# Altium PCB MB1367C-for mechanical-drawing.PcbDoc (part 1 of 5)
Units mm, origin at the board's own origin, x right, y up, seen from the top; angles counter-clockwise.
Board outline 70 x 82.5 mm, 4 copper layers (Top Layer, Signal Layer 1, Signal Layer 2, Bottom Layer), stack 1.614 mm thick; 191 components, 143 nets, 808 pads, 920 vias.
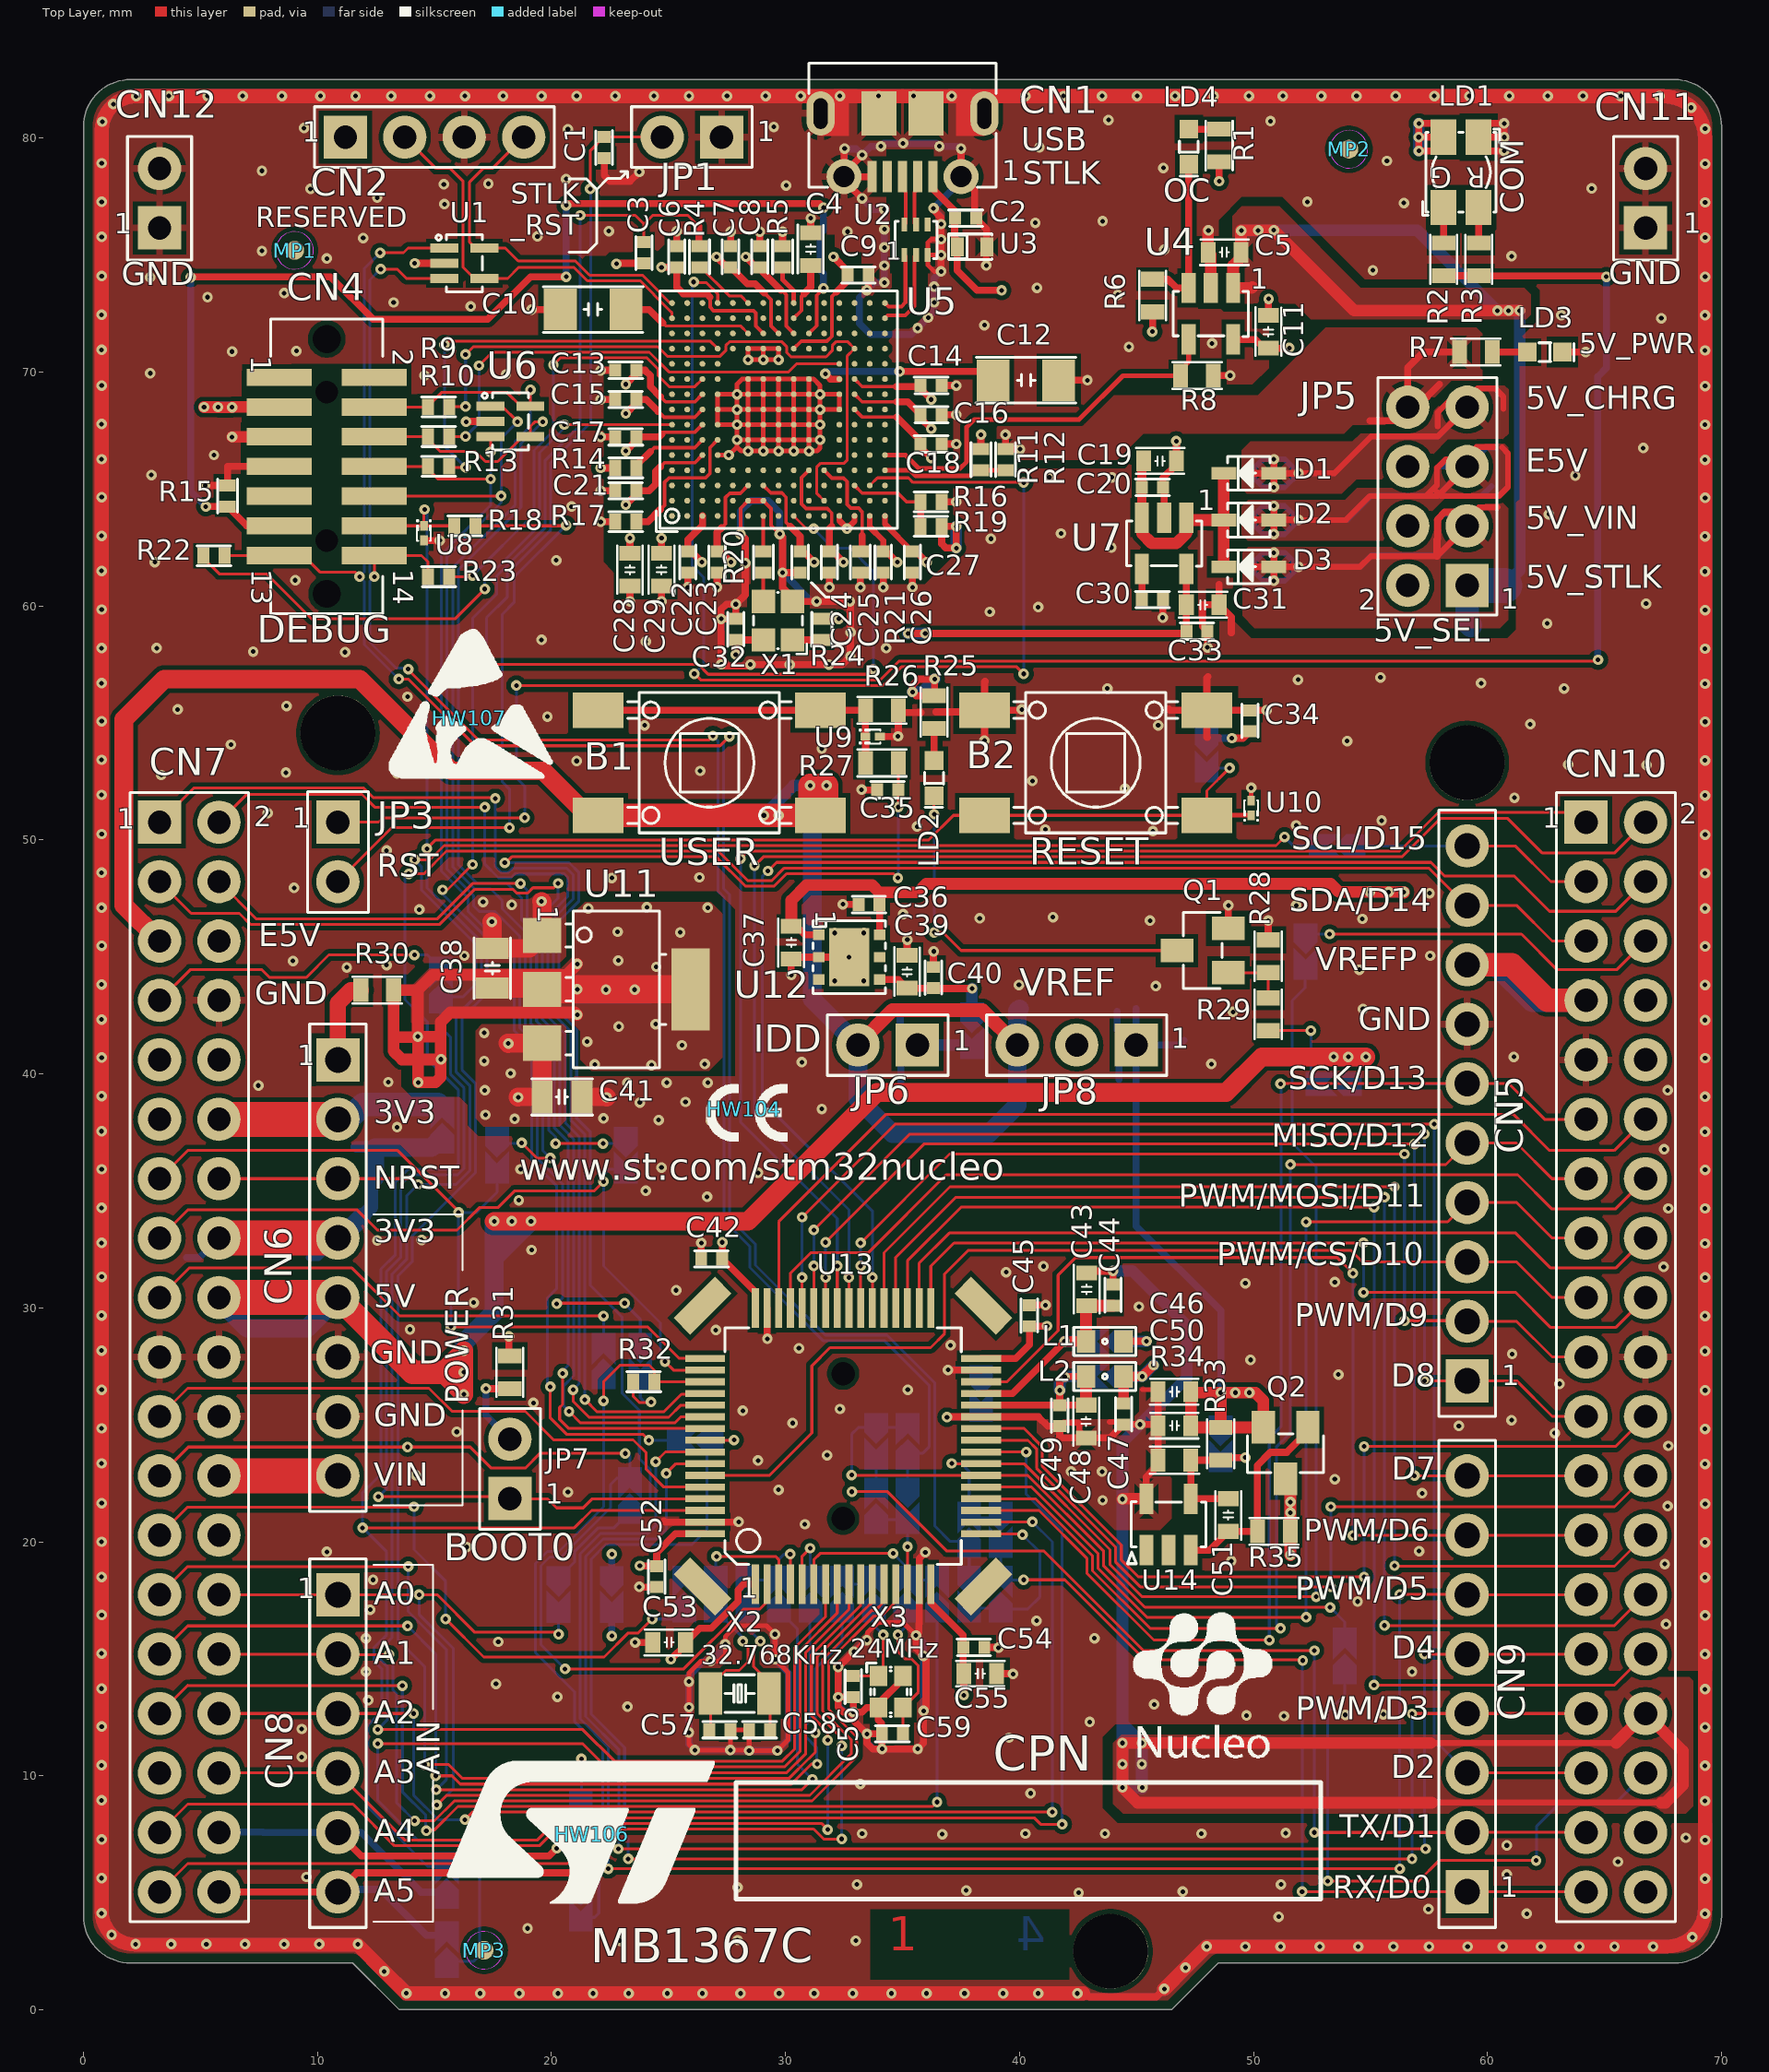
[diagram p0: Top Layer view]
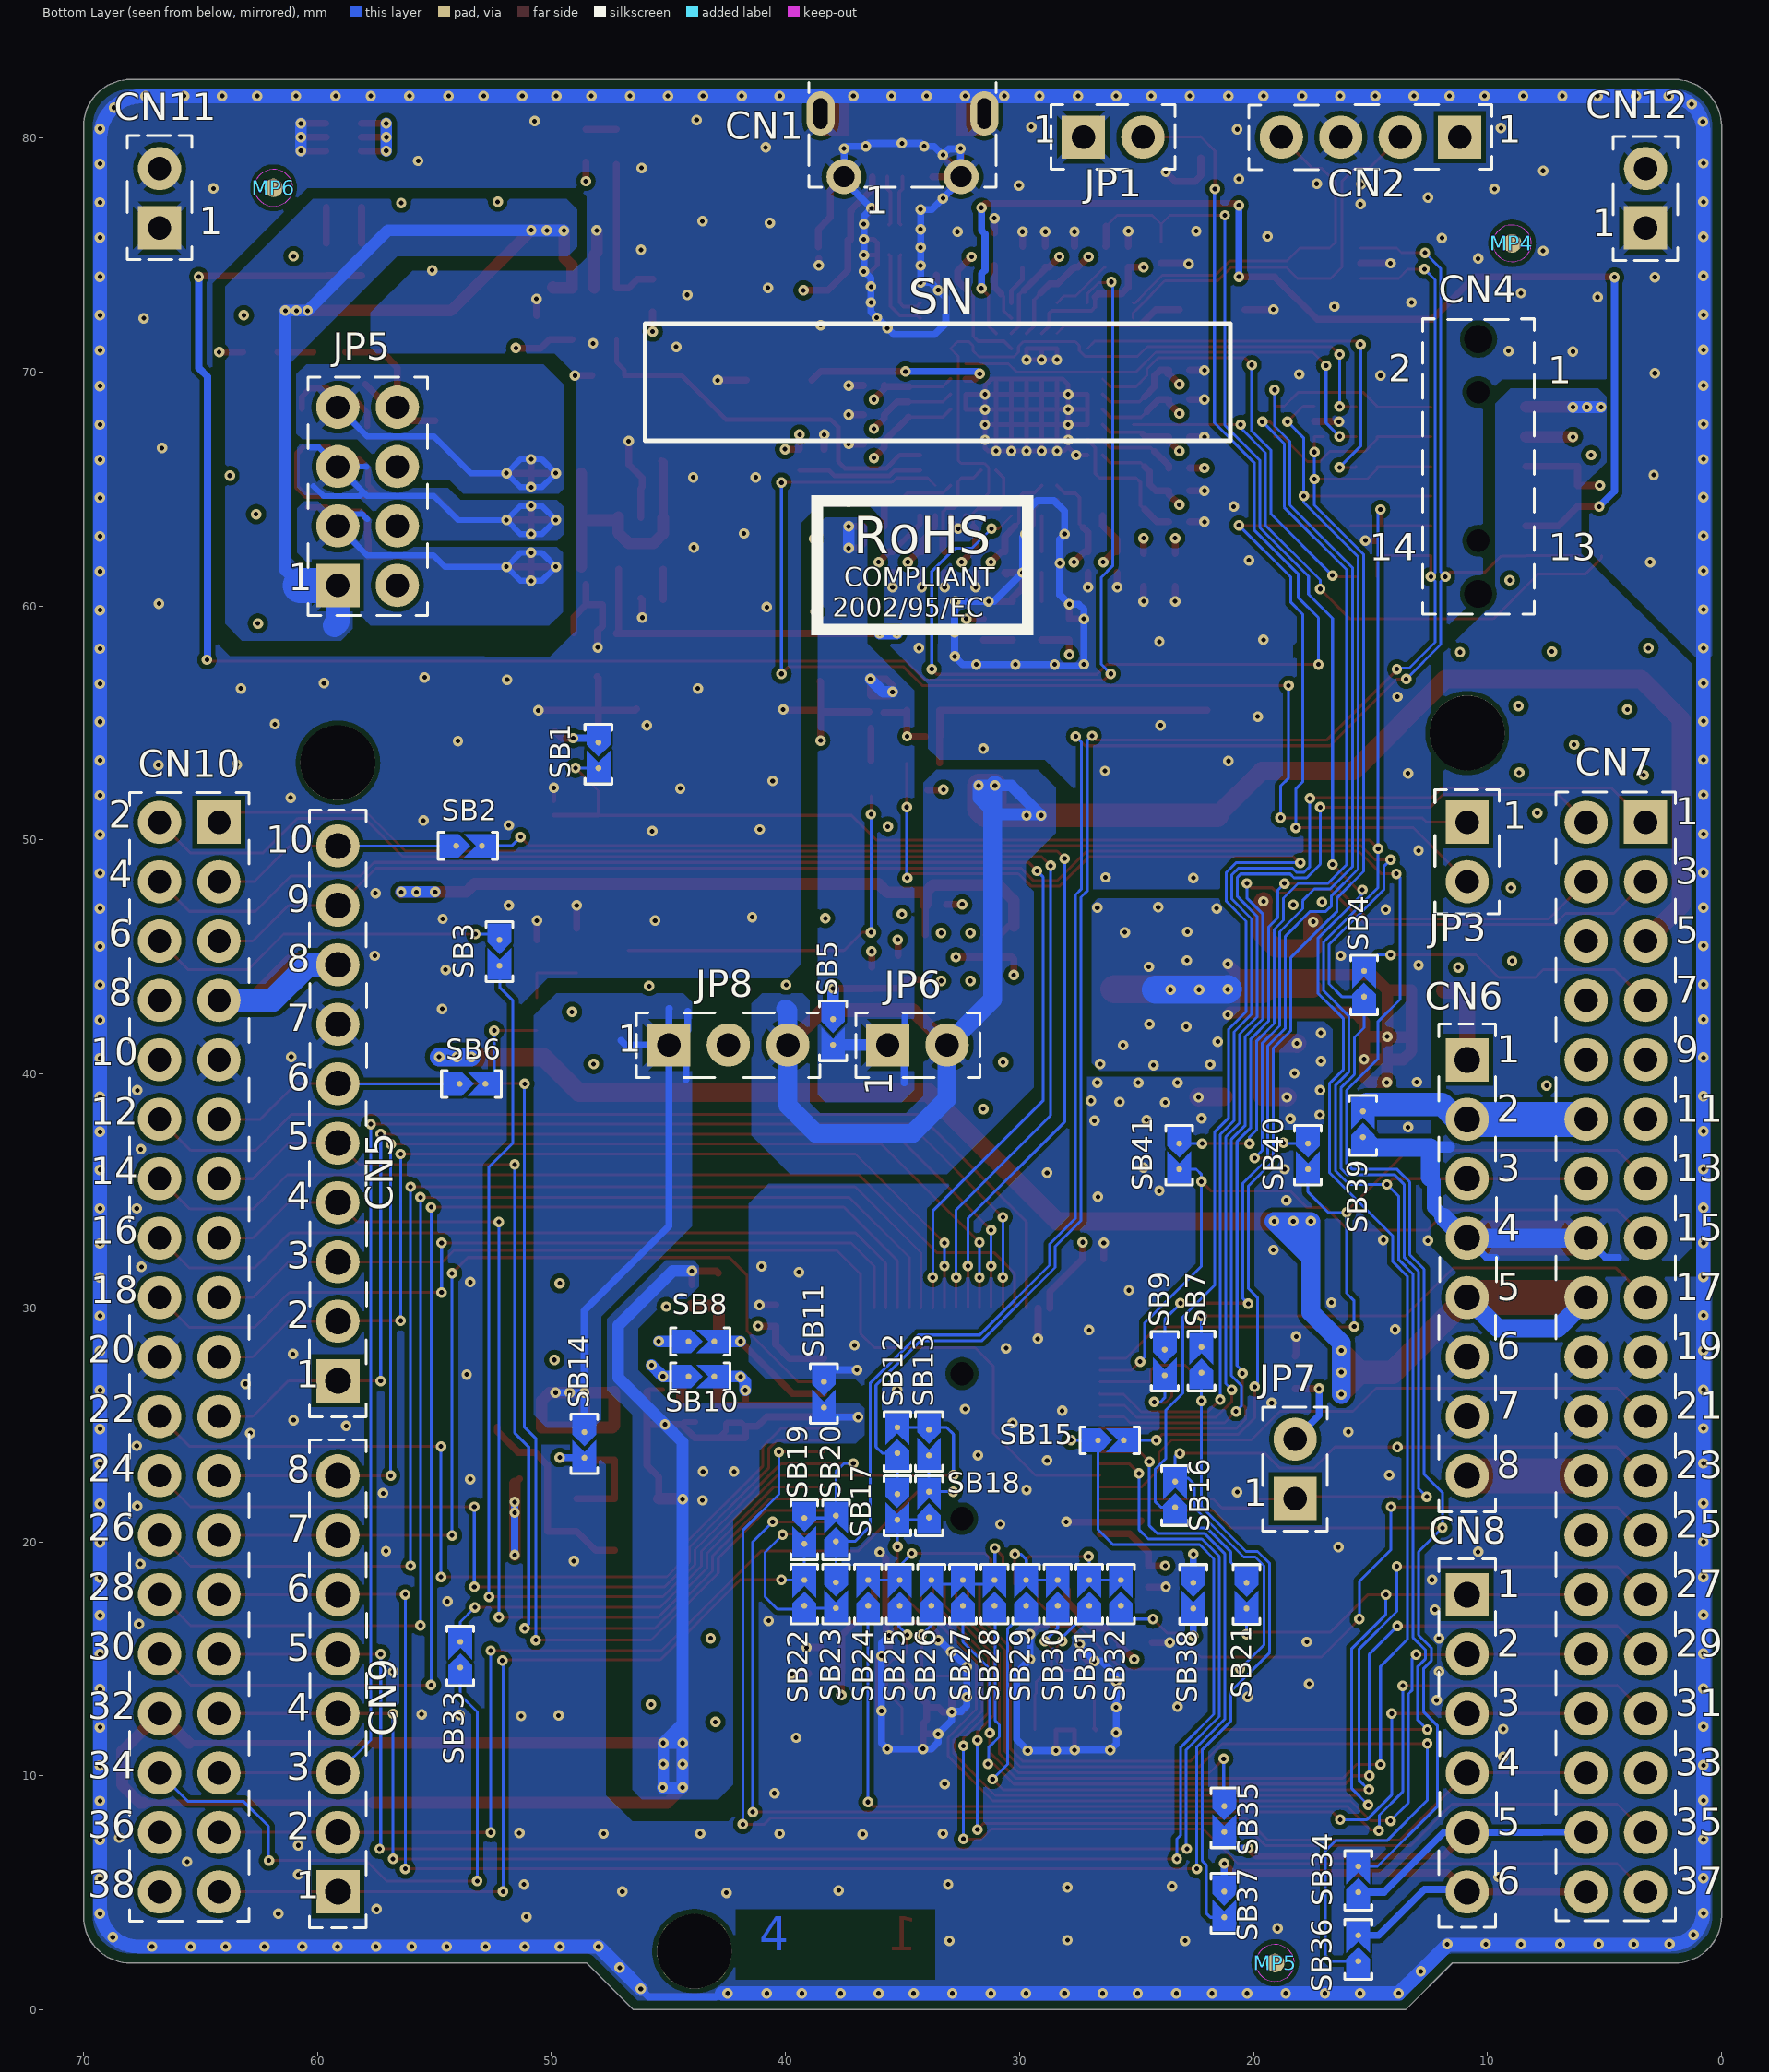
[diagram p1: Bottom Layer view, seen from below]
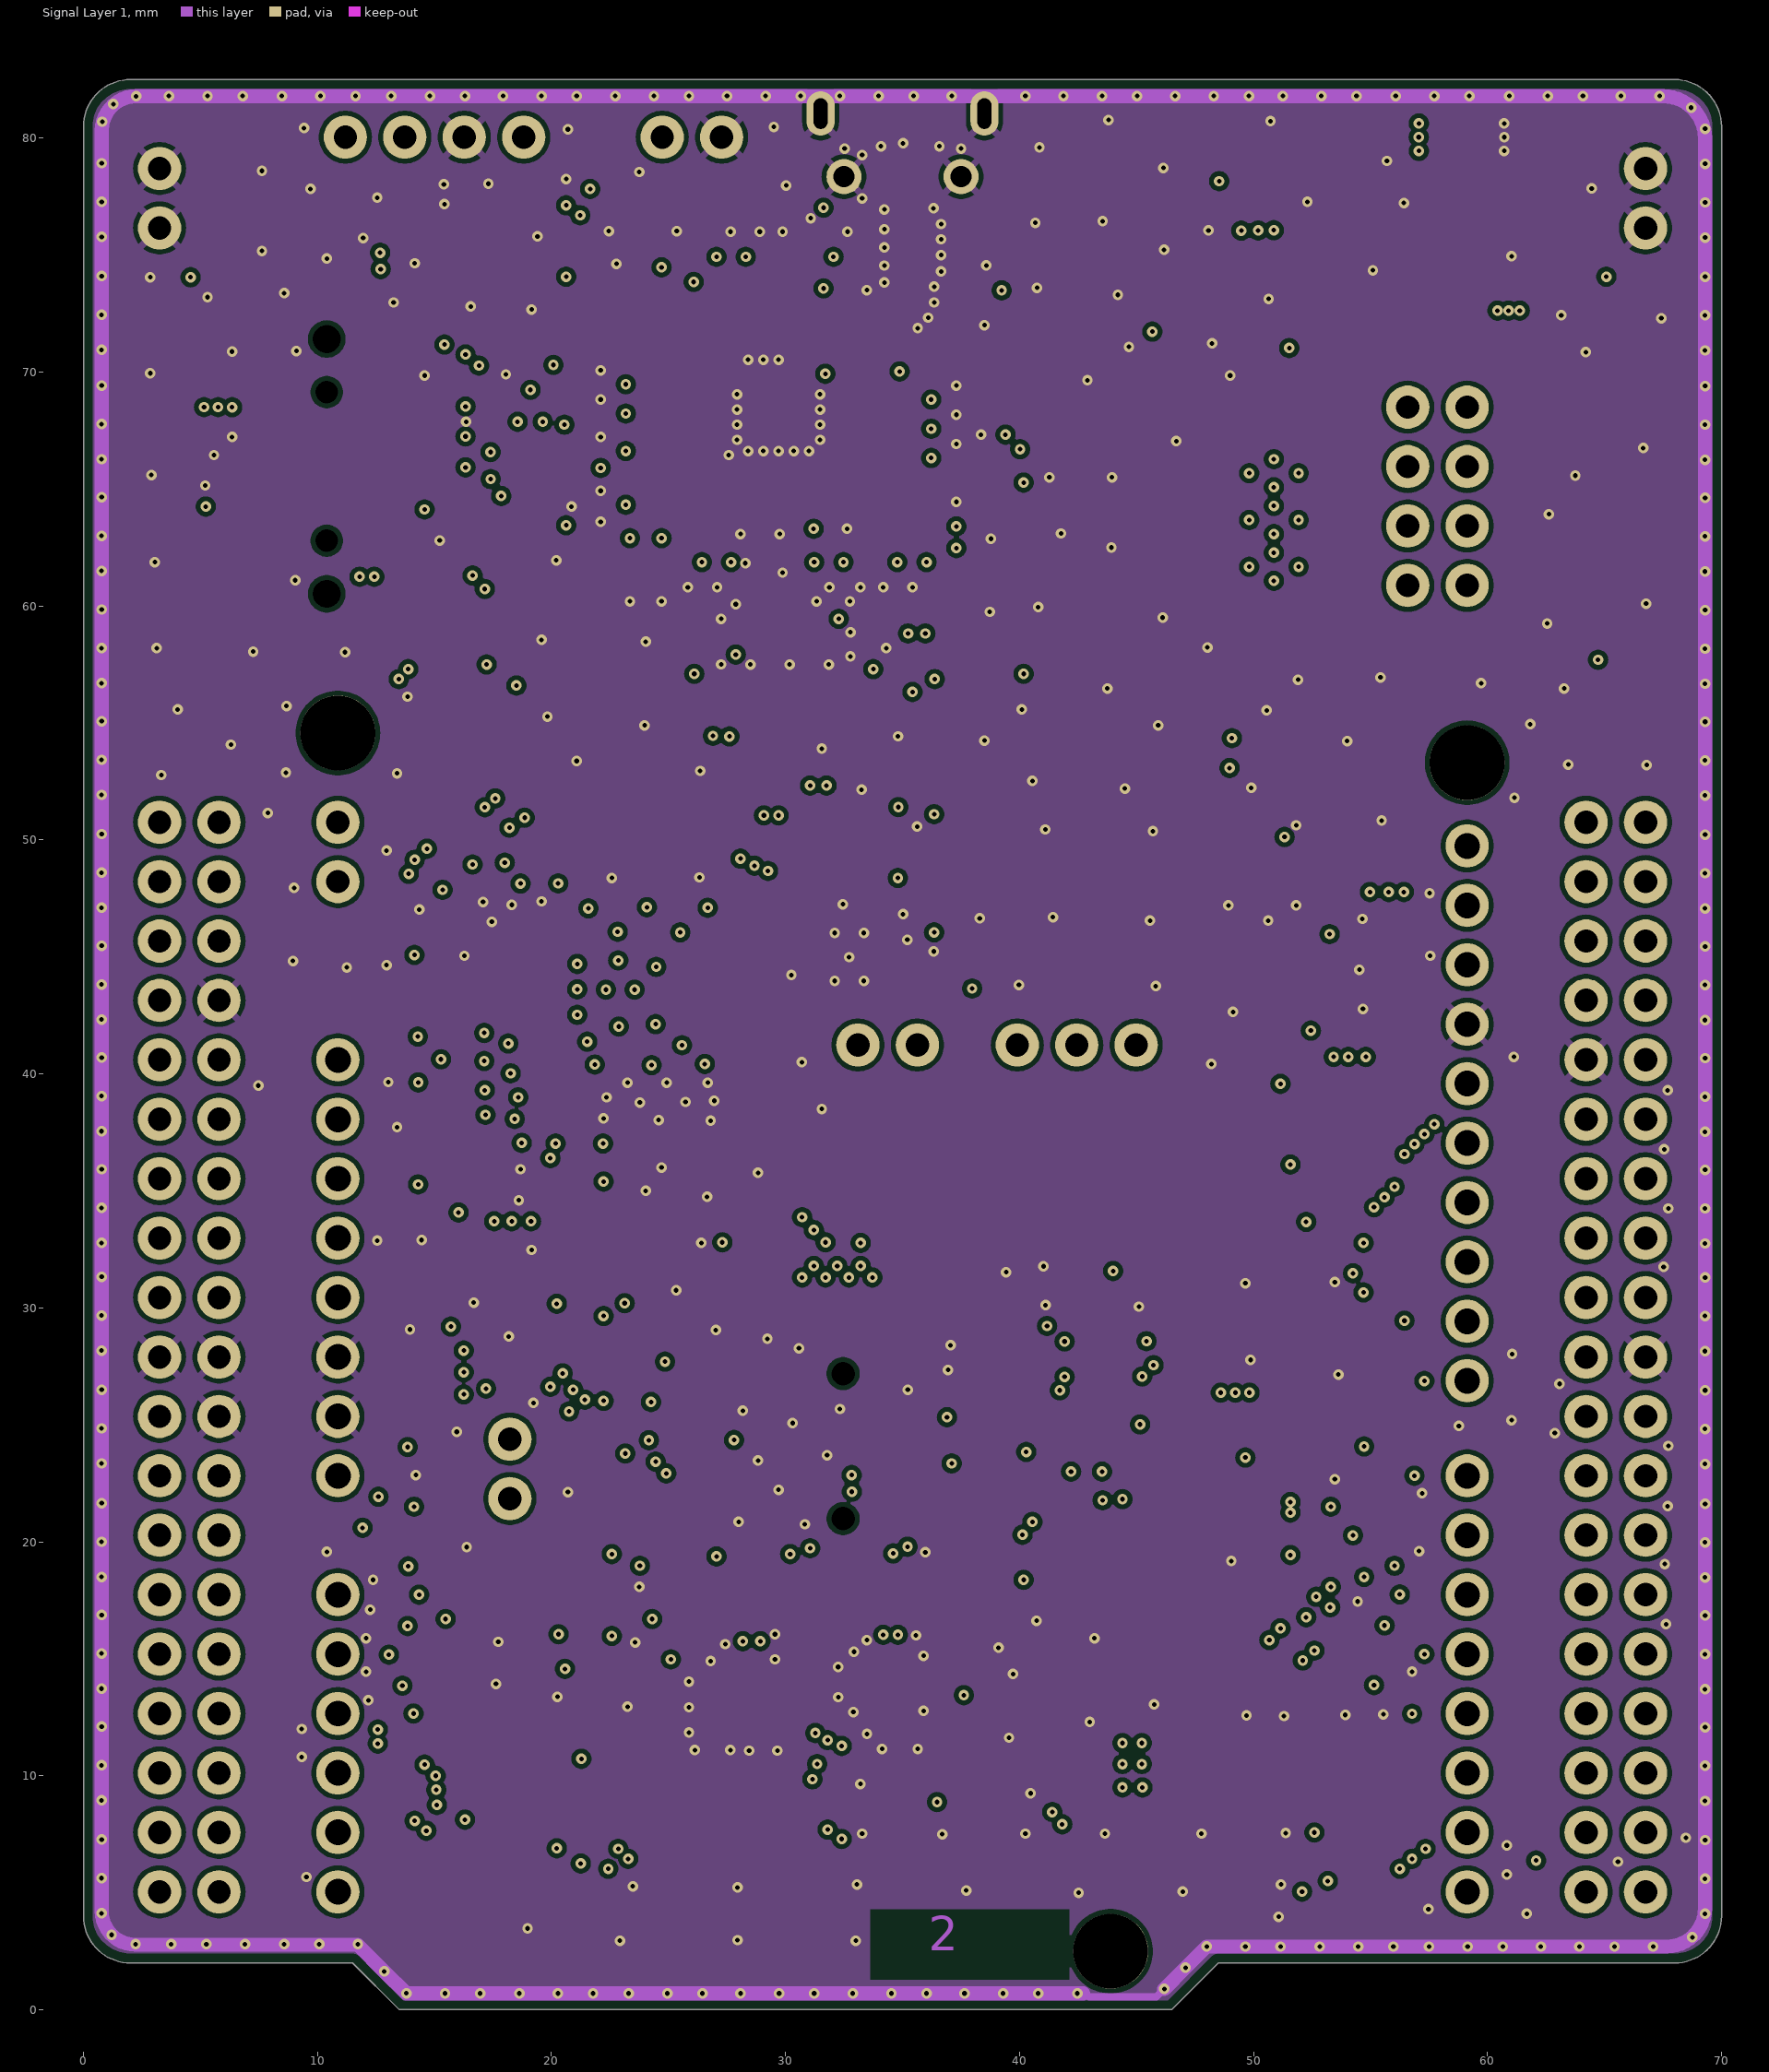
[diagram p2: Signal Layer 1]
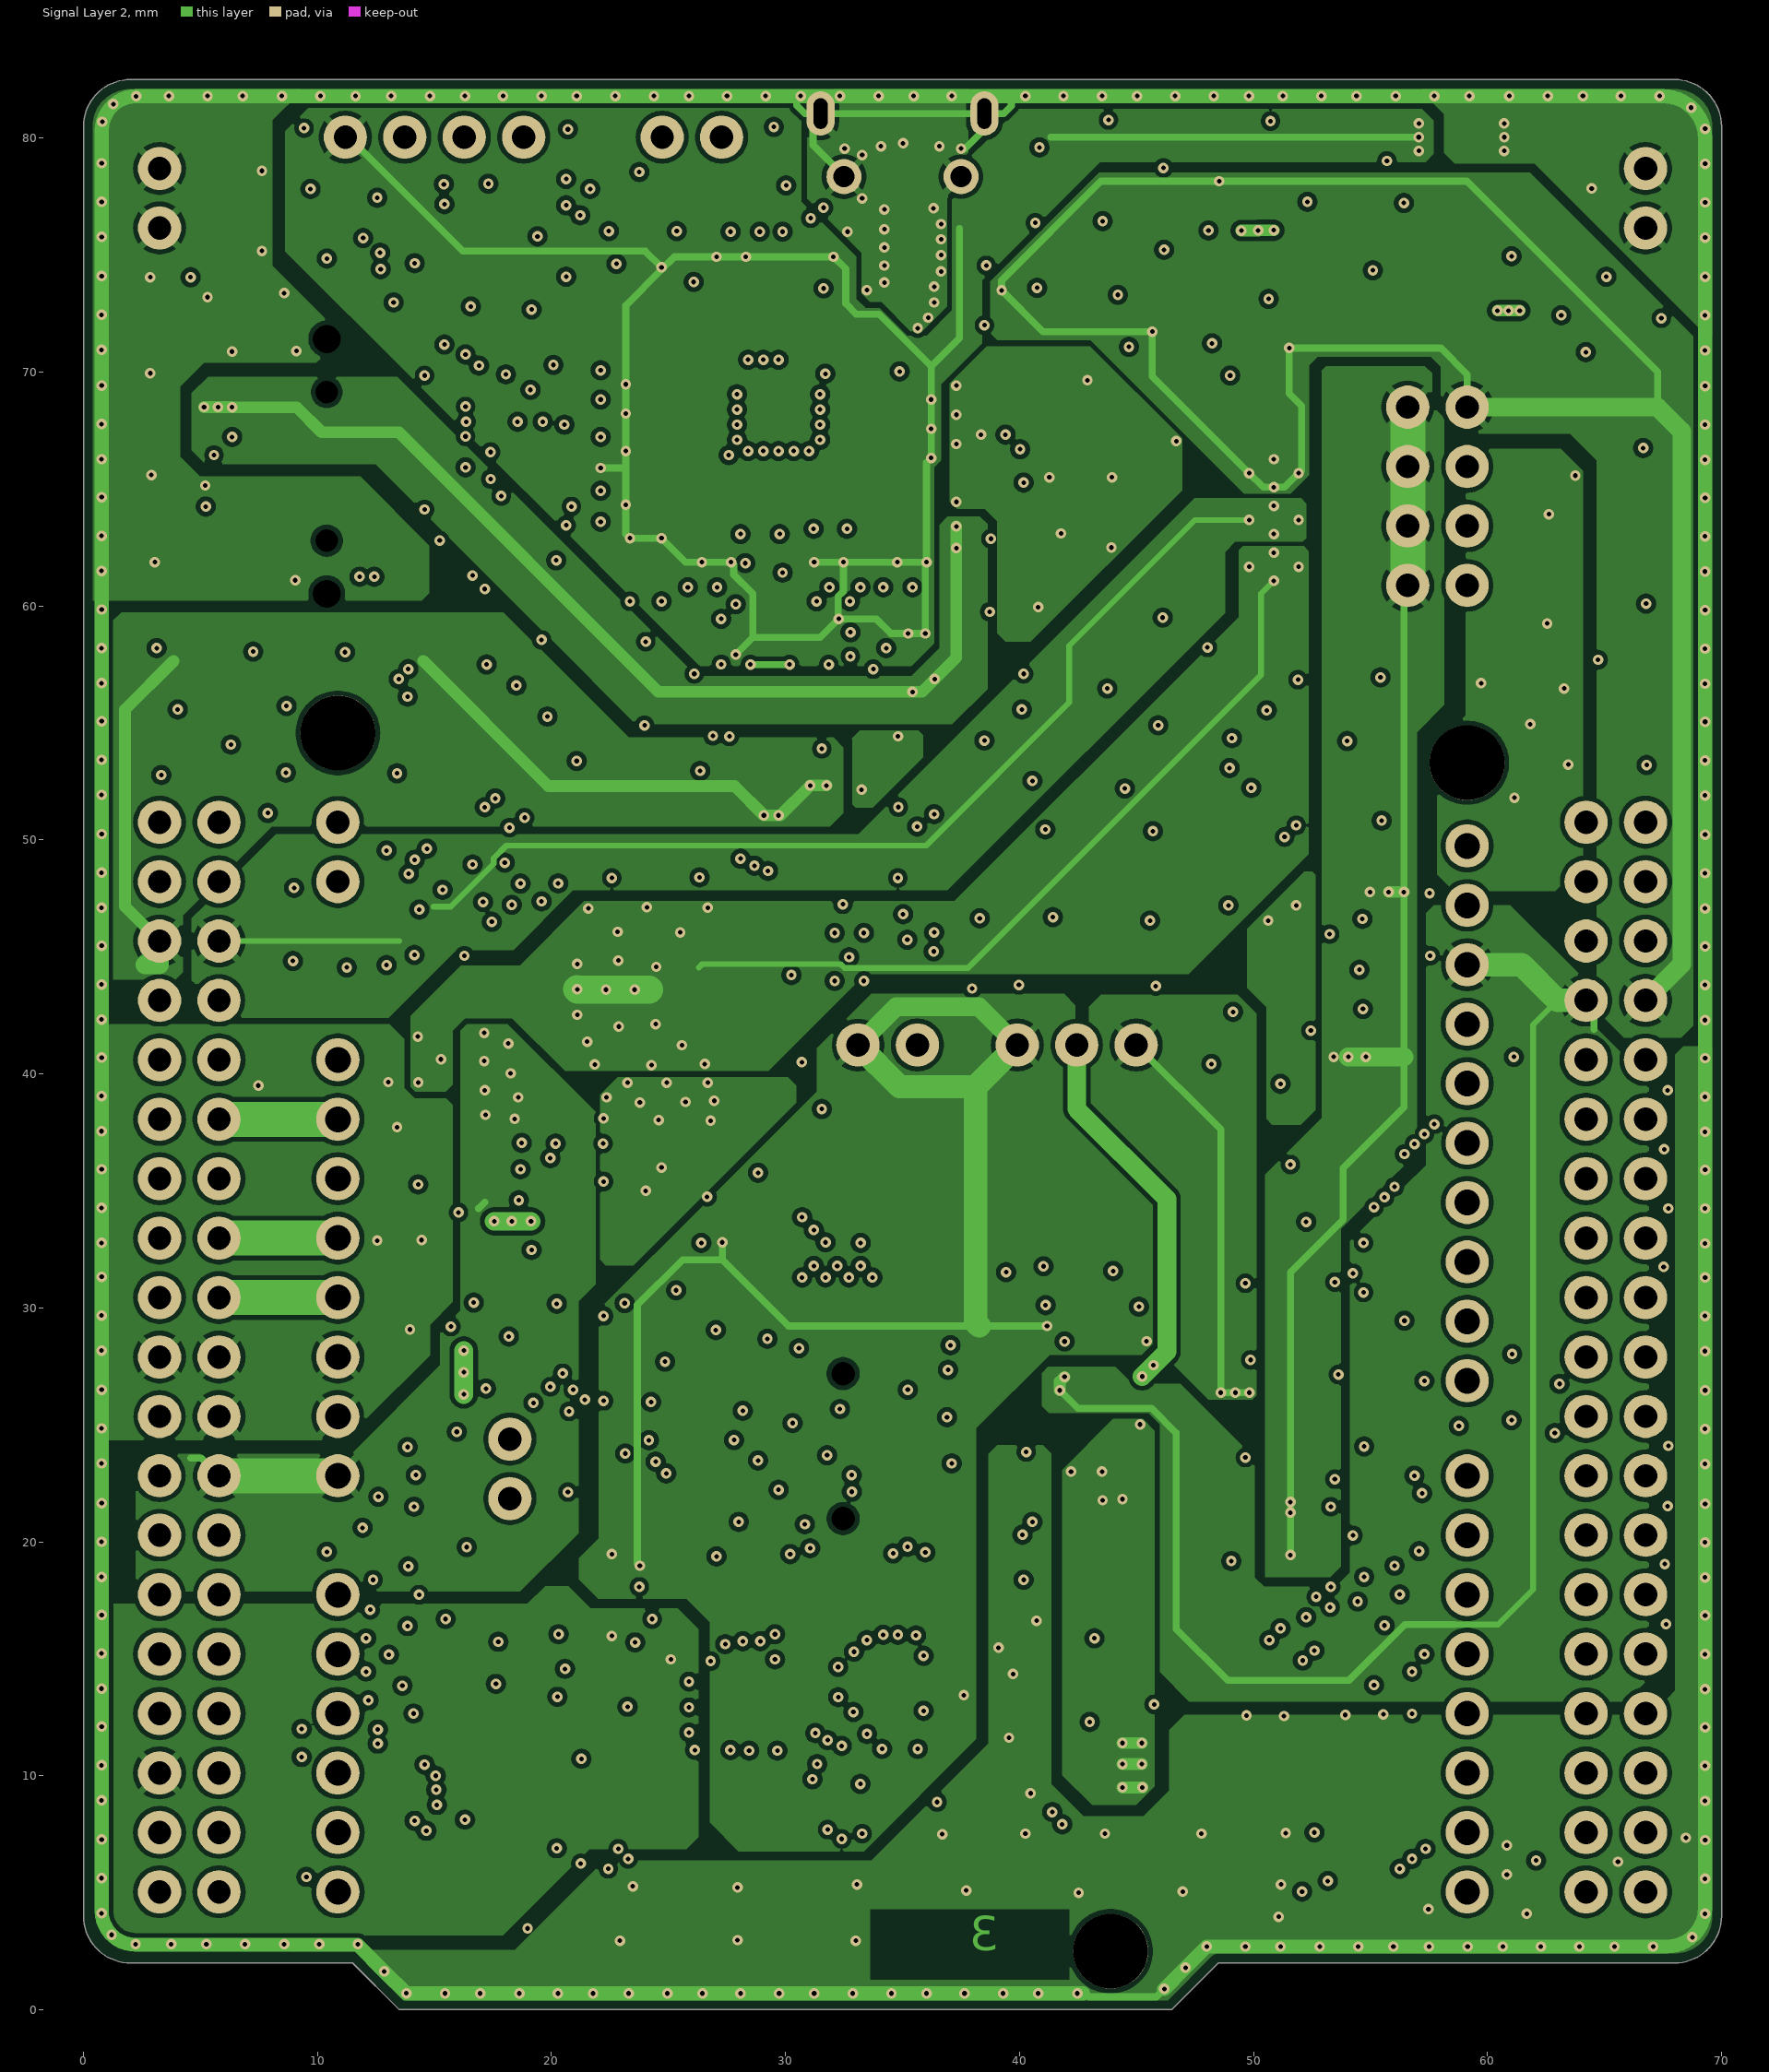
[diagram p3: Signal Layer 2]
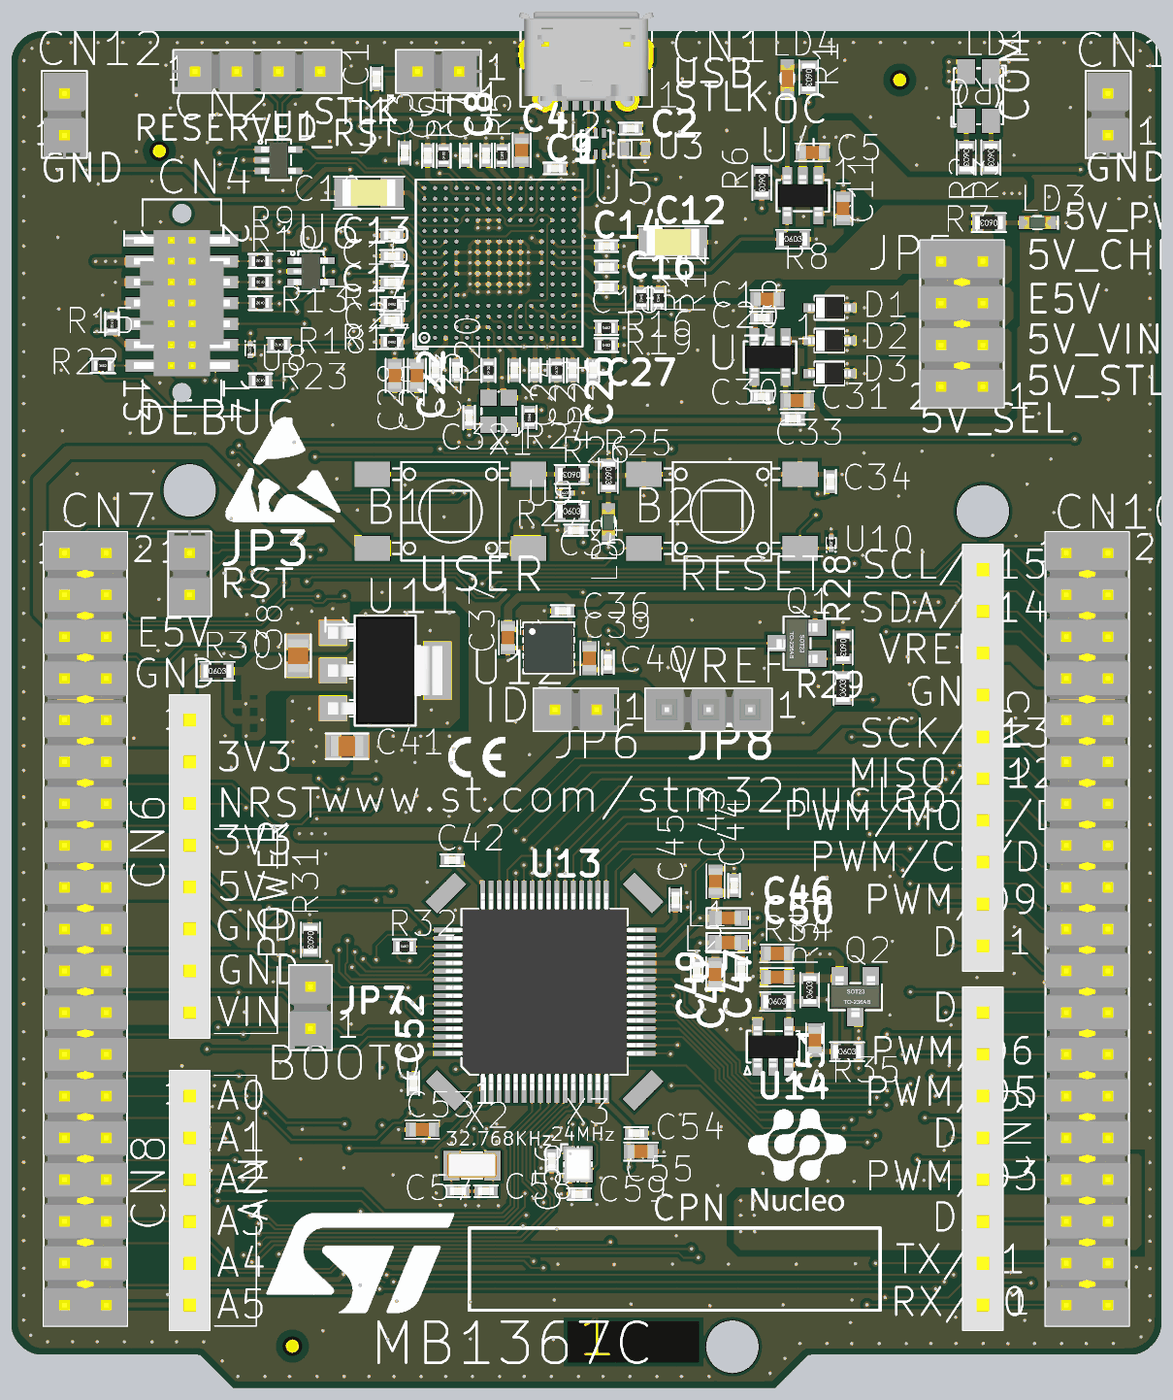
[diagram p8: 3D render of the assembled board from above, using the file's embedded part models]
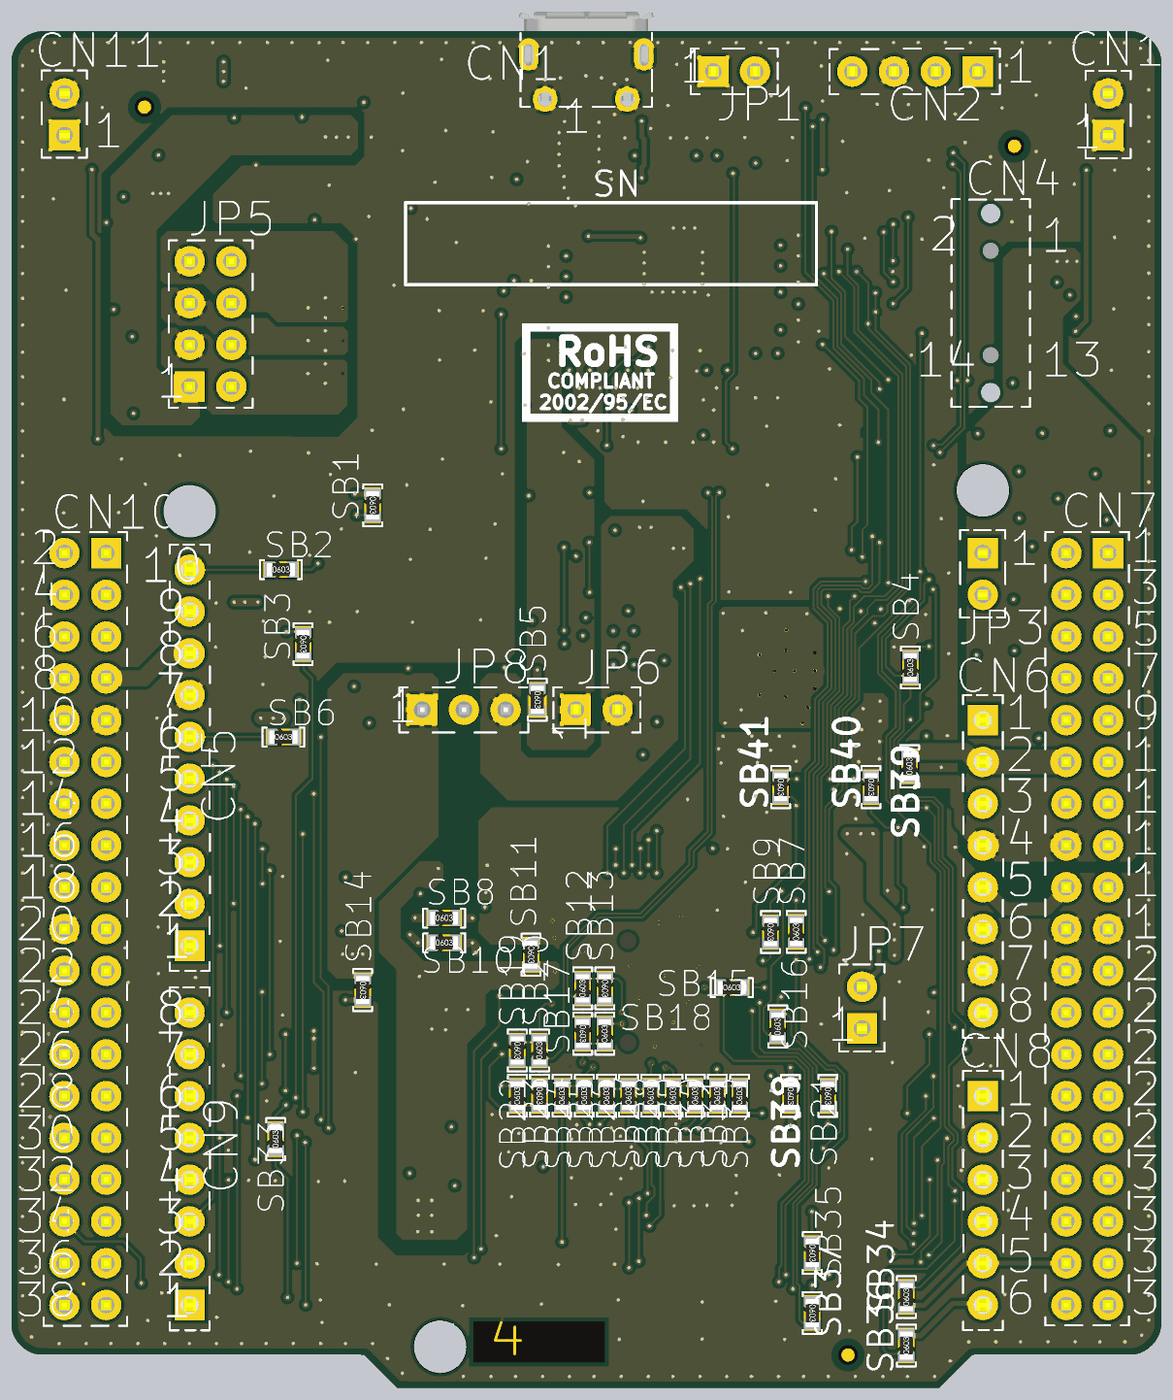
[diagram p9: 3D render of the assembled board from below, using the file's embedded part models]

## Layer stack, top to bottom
Top Solder: solder mask 0.015, Solder Resist, Dk 3.5
Top Layer: signal copper 0.042
Dielectric 1: prepreg 0.106, PP-IT-180A, Dk 4.2
Signal Layer 1: signal copper 0.035
Dielectric 2: core 1.248, FR4, Dk 4.2
Signal Layer 2: signal copper 0.035
Dielectric 3: prepreg 0.106, PP-IT-180A, Dk 4.2
Bottom Layer: signal copper 0.042
Bottom Solder: solder mask 0.015, Solder Resist, Dk 3.5

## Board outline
2,2 11.5,2 13.5,0 46.5,0 48.5,2 68,2 ccw(c68,4) 70,4 70,80.5 ccw(c68,80.5) 68,82.5 2,82.5 ccw(c2,80.5) 0,80.5 0,4 ccw(c2,4)

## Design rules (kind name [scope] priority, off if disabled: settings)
BoardOutlineClearance [All] p1: gap=0.4 ignorepadtopadclearanceinfootprint=FALSE
Clearance Clearance_USB [InNetClass('USB')] p1: gap=0.12 ignorepadtopadclearanceinfootprint=TRUE except(0.2: Arc-THPad Arc-Fill Track-THPad Track-Fill SMDPad-SMDPad SMDPad-THPad SMDPad-Fill THPad-THPad THPad-Fill Via-Fill Fill-Fill; 0.5: Arc-Poly Track-Poly SMDPad-Poly THPad-Poly Via-Poly Fill-Poly Poly-Poly)
Clearance [All] p2: gap=0.12 ignorepadtopadclearanceinfootprint=TRUE except(0.2: Arc-THPad Arc-Fill Arc-Poly Track-THPad Track-Fill Track-Poly SMDPad-SMDPad SMDPad-THPad SMDPad-Fill SMDPad-Poly THPad-THPad THPad-Fill THPad-Poly Via-Fill Via-Poly Fill-Fill Fill-Poly Poly-Poly)
ComponentClearance [All] p1 off: gap=0.025 collisioncheckmode=3 verticalgap=2540 showdistances=TRUE
DiffPairsRouting DiffPairsRouting_USB [InDifferentialPairClass('DIFF_USB')] p1: maxlimit=0.226 minlimit=0.226 mostfreqgap=0.226 toplayer_minwidth=0.16 toplayer_maxwidth=0.16 toplayer_prefwidth=0.16 midlayer1_minwidth=0.16 midlayer1_maxwidth=0.16 midlayer1_prefwidth=0.16 midlayer2_minwidth=0.16 midlayer2_maxwidth=0.16 midlayer2_prefwidth=0.16 bottomlayer_minwidth=0.16 bottomlayer_maxwidth=0.16 bottomlayer_prefwidth=0.16 maxuncoupledlength=50
FanoutControl Fanout_BGA [IsBGA] p1: bgadir=Out bgaviamode=Closest fanoutstyle=Auto fanoutdirection=Alternating viagrid=0.025 // Fanout_BGA (Default Rule)
FanoutControl Fanout_LCC [IsLCC] p2: bgadir=Out bgaviamode=Closest fanoutstyle=Auto fanoutdirection=Alternating viagrid=0.025 // Fanout_LCC (Default Rule)
FanoutControl Fanout_SOIC [IsSOIC] p3: bgadir=Out bgaviamode=Closest fanoutstyle=Auto fanoutdirection=Alternating viagrid=0.025 // Fanout_SOIC (Default Rule)
FanoutControl Fanout_Small [(CompPinCount < 5)] p4: bgadir=Out bgaviamode=Closest fanoutstyle=Auto fanoutdirection=OutThenIn viagrid=0.025 // Fanout_Small (Default Rule)
FanoutControl Fanout_Default [All] p5: bgadir=Out bgaviamode=Closest fanoutstyle=Auto fanoutdirection=Alternating viagrid=0.025 // Fanout_Default (Default Rule)
Height [All] p1 off: minheight=0 maxheight=100 prefheight=0.5
HoleSize [All] p1: absolutevalues=TRUE maxlimit=10 minlimit=0.15 maxpercent=80.000 minpercent=20.000
HoleToHoleClearance [All] p1: gap=0.25 allowstackedmicrovias=TRUE
Length Length_USB [InNetClass('USB')] p1: maxlimit=50 minlimit=1
MatchedLengths [InDifferentialPairClass('DIFF_USB')] p1: tolerance=0.2 checknetsindiffpair=TRUE checkdiffpairvsdiffpair=FALSE checkxsignals=FALSE checkothers=FALSE
MinimumSolderMaskSliver [All] p1: minsoldermaskwidth=0
PlaneClearance [All] p1: clearance=0.6
PolygonConnect PolygonConnect_6 [All vs IsNamedPolygon('GND_L01_P086')] p1: thpad.connectstyle=Relief thpad.reliefconductorwidth=0.3 thpad.reliefentries=4 thpad.polygonreliefangle="90 Angle" thpad.airgapwidth=0.2 smdpad.connectstyle=NoConnect smdpad.reliefconductorwidth=0.254 smdpad.reliefentries=4 smdpad.polygonreliefangle="90 Angle" smdpad.airgapwidth=0.254 via.connectstyle=Direct via.reliefconductorwidth=0.254 via.reliefentries=4 via.polygonreliefangle="90 Angle" via.airgapwidth=0.254
PolygonConnect PolygonConnect_5 [All vs IsNamedPolygon('GND_L01_P084')] p2: thpad.connectstyle=Relief thpad.reliefconductorwidth=0.3 thpad.reliefentries=4 thpad.polygonreliefangle="90 Angle" thpad.airgapwidth=0.2 smdpad.connectstyle=NoConnect smdpad.reliefconductorwidth=0.254 smdpad.reliefentries=4 smdpad.polygonreliefangle="90 Angle" smdpad.airgapwidth=0.254 via.connectstyle=Direct via.reliefconductorwidth=0.254 via.reliefentries=4 via.polygonreliefangle="90 Angle" via.airgapwidth=0.254
PolygonConnect PolygonConnect_4 [All vs IsNamedPolygon('GND_L01_P082')] p3: thpad.connectstyle=Relief thpad.reliefconductorwidth=0.3 thpad.reliefentries=4 thpad.polygonreliefangle="90 Angle" thpad.airgapwidth=0.2 smdpad.connectstyle=NoConnect smdpad.reliefconductorwidth=0.254 smdpad.reliefentries=4 smdpad.polygonreliefangle="90 Angle" smdpad.airgapwidth=0.254 via.connectstyle=Direct via.reliefconductorwidth=0.254 via.reliefentries=4 via.polygonreliefangle="90 Angle" via.airgapwidth=0.254
PolygonConnect PolygonConnect_3 [All vs IsNamedPolygon('GND_L01_P010')] p4: thpad.connectstyle=Relief thpad.reliefconductorwidth=0.3 thpad.reliefentries=4 thpad.polygonreliefangle="90 Angle" thpad.airgapwidth=0.2 smdpad.connectstyle=Direct smdpad.reliefconductorwidth=0.254 smdpad.reliefentries=4 smdpad.polygonreliefangle="90 Angle" smdpad.airgapwidth=0.254 via.connectstyle=Direct via.reliefconductorwidth=0.254 via.reliefentries=4 via.polygonreliefangle="90 Angle" via.airgapwidth=0.254
PolygonConnect PolygonConnect_2 [All vs IsNamedPolygon('VIN_L01_P008')] p5: thpad.connectstyle=Relief thpad.reliefconductorwidth=0.3 thpad.reliefentries=4 thpad.polygonreliefangle="90 Angle" thpad.airgapwidth=0.2 smdpad.connectstyle=Direct smdpad.reliefconductorwidth=0.254 smdpad.reliefentries=4 smdpad.polygonreliefangle="90 Angle" smdpad.airgapwidth=0.254 via.connectstyle=Direct via.reliefconductorwidth=0.254 via.reliefentries=4 via.polygonreliefangle="90 Angle" via.airgapwidth=0.254
PolygonConnect PolygonConnect_1 [All vs IsNamedPolygon('5V_VIN_L01_P004')] p6: thpad.connectstyle=Relief thpad.reliefconductorwidth=0.3 thpad.reliefentries=4 thpad.polygonreliefangle="90 Angle" thpad.airgapwidth=0.2 smdpad.connectstyle=Direct smdpad.reliefconductorwidth=0.254 smdpad.reliefentries=4 smdpad.polygonreliefangle="90 Angle" smdpad.airgapwidth=0.254 via.connectstyle=Direct via.reliefconductorwidth=0.254 via.reliefentries=4 via.polygonreliefangle="90 Angle" via.airgapwidth=0.254
PolygonConnect [All vs IsNamedPolygon('GND_L01_P006')] p7: thpad.connectstyle=Relief thpad.reliefconductorwidth=0.3 thpad.reliefentries=4 thpad.polygonreliefangle="90 Angle" thpad.airgapwidth=0.2 smdpad.connectstyle=Direct smdpad.reliefconductorwidth=0.254 smdpad.reliefentries=4 smdpad.polygonreliefangle="90 Angle" smdpad.airgapwidth=0.254 via.connectstyle=Direct via.reliefconductorwidth=0.254 via.reliefentries=4 via.polygonreliefangle="90 Angle" via.airgapwidth=0.254
PolygonConnect PolygonConnect__DEFAULT [All] p8: thpad.connectstyle=Relief thpad.reliefconductorwidth=0.3 thpad.reliefentries=4 thpad.polygonreliefangle="45 Angle" thpad.airgapwidth=0.2 smdpad.connectstyle=Relief smdpad.reliefconductorwidth=0.3 smdpad.reliefentries=4 smdpad.polygonreliefangle="45 Angle" smdpad.airgapwidth=0.2 via.connectstyle=Direct via.reliefconductorwidth=0.254 via.reliefentries=4 via.polygonreliefangle="45 Angle" via.airgapwidth=0.254
RoutingVias [All] p1: holewidth=0.2 width=0.45 viastyle="Through Hole" minholewidth=0.2 minwidth=0.45 maxholewidth=0.2 maxwidth=0.45
SilkToSilkClearance [All] p1: silktosilkclearance=0
SilkToSolderMaskClearance [IsPad] p1: minsilkscreentomaskgap=0 clearancetoexposedcopper=TRUE
SolderMaskExpansion [All] p1: expansion=0.05
Width Width_ALIMS [InNetClass('ALIMS')] p1: maxlimit=10 minlimit=0.12 preferedwidth=0.3
Width Width_GND [InNetClass('GND')] p2: maxlimit=10 minlimit=0.12 preferedwidth=0.3 minimp=50.000000 maximp=50.000000 favimp=50.000000
Width [All] p3: maxlimit=10 minlimit=0.12 preferedwidth=0.12
16 further rules are at their usual default settings.

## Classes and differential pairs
net class USB: USB_DEV_HS_CN_N USB_DEV_HS_CN_P USB_DEV_HS_N USB_DEV_HS_P
net class GND: AGND AVDD GND GNDDetect
net class ALIMS: 3V3 3V3_STLK 5V 5V_USB_CHGR 5V_USB_STLK 5V_VIN E5V VDD VIN VREF VREFP
differential pair class DIFF_USB: USB_DEV_HS USB_DEV_HS_CN
differential pair USB_DEV_HS_CN: +USB_DEV_HS_CN_P -USB_DEV_HS_CN_N
differential pair USB_DEV_HS: +USB_DEV_HS_P -USB_DEV_HS_N

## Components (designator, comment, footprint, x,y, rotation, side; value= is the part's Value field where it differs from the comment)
B1 "" SWI_WEALTHMETAL_TD-0341_4P_BLUE 26.745,53.3 r90 top locked value=SW_BLUE
B2 "" SWI_WEALTHMETAL_TD-0341_4P_BLACK 43.255,53.3 r90 top locked value=SW_BLACK
C1 "" C0402 22.25,79.6 r90 top value=100nF
C2 "" C0402 37.7,76.575 r180 top value=100pF
C3 "" C0402 23.95,75.1 r90 top value=20pF
C4 "" C0603 31.075,75.25 r270 top value=2.2uF
C5 "" C0603 48.76,75.12 r0 top value=1uF
C6 "" C0402 25.35,74.925 r270 top value=100nF
C7 "" C0402 27.65,74.925 r270 top value=100nF
C8 "" C0402 28.9,74.925 r270 top value=100nF
C9 "" C0402 33.1,74.15 r180 top value=100nF
C10 "" C1206_H1P15 21.775,72.675 r0 top value=2.2uF
C11 "" C0603 50.635,71.72 r270 top value=1uF
C12 "" C1206_H1P15 40.275,69.65 r180 top value=2.2uF
C13 "" C0402 23.175,70.075 r0 top value=100nF
C14 "" C0402 36.225,69.425 r180 top value=100nF
C15 "" C0402 23.175,68.825 r0 top value=100nF
C16 "" C0402 36.225,68.175 r180 top value=100nF
C17 "" C0402 23.175,67.225 r0 top value=100nF
C18 "" C0402 36.225,66.925 r180 top value=100nF
C19 "" C0603 46.005,66.2 r180 top value=1uF
C20 "" C0402 45.68,65.075 r180 top value=100nF
C21 "" C0402 23.175,64.925 r0 top value=100nF
C22 "" C0402 25.825,61.875 r90 top value=100nF
C23 "" C0402 27.075,61.875 r90 top value=100nF
C24 "" C0402 30.625,61.875 r90 top value=100nF
C25 "" C0402 31.875,61.875 r90 top value=100nF
C26 "" C0402 34.175,61.875 r90 top value=100nF
C27 "" C0402 35.425,61.875 r90 top value=100nF
C28 "" C0603 23.35,61.55 r90 top value=4.7uF
C29 "" C0603 24.7,61.55 r90 top value=1uF
C30 "" C0402 45.68,60.275 r180 top value=10nF
C31 "" C0603 47.83,60.05 r180 top value=1uF
C32 "" C0402 27.875,59 r270 top value=100nF
C33 "" C0402 47.58,58.925 r180 top value=100nF
C34 "" C0402 49.845,55.09 r270 top value=100nF
C35 "" C0402 34.37,52.14 r0 top value=100nF
C36 "" C0402 33.57,47.24 r0 top value=100nF
C37 "" C0603 30.245,45.615 r90 top value=1uF
C38 "" C0805 17.47,44.515 r270 top value=10uF
C39 "" C0603 35.195,44.365 r270 top value=1uF
C40 "" C0402 36.32,44.115 r270 top value=100nF
C41 "" C0805 20.445,39.015 r180 top value=10uF
C42 "" C0402 26.845,32.09 r0 top value=100nF
C43 "" C0603 42.87,30.79 r270 top value=1uF
C44 "" C0402 43.995,30.54 r270 top value=100nF
C45 "" C0402 40.42,29.665 r270 top value=100nF
C46 "Capacitor" C0603 46.62,26.415 r0 top value=10uF
C47 "" C0402 44.445,25.465 r90 top value=100nF
C48 "" C0603 42.845,25.14 r270 top value=1uF
C49 "" C0402 41.72,25.39 r270 top value=100nF
C50 "" C0603 46.62,24.965 r0 top value=100nF
C51 "Capacitor" C0603 48.92,21.14 r90 top value=100pF
C52 "" C0402 24.495,18.515 r90 top value=100nF
C53 "" C0603 25.025,15.7 r0 top value=1uF
C54 "" C0402 38.045,15.49 r180 top value=100nF
C55 "" C0603 38.32,14.365 r180 top value=4.7uF
C56 "" C0402 32.895,13.815 r90 top value=6.8pF
C57 "" C0402 27.195,11.965 r0 top value=5.1pF
C58 "" C0402 28.895,11.965 r180 top value=5.1pF
C59 "" C0402 34.57,11.79 r0 top value=6.8pF
CN1 "" CON_USBMICROB_MOLEX_105017-0001_H2P90 35,82.5 r180 top locked value=USB_uB_105017-0001
CN2 "" CON_SAMTEC_TSW-104-07-G-S 15,80.04 r0 top value="Header 4x1"
CN4 "" CON_STDC14_Receiver_MEDIUM 10.395,65.965 r270 top locked value=STDC14
CN5 "" CON_SAMTEC_SSW-110-03-X-S 59.13,38.314 r90 top locked value="Socket 10x1"
CN6 "" CON_SAMTEC_SSW-108-03-X-S 10.87,31.71 r270 top locked value="Socket 8x1"
CN7 "" CON_SAMTEC_TSW-119-09-X-D 4.52,27.9 r270 top locked value="Header 19x2"
CN8 "" CON_SAMTEC_SSW-106-03-X-S 10.87,11.39 r270 top locked value="Socket 6x1"
CN9 "" CON_SAMTEC_SSW-108-03-X-S 59.13,13.93 r90 top value="Socket 8x1"
CN10 "" CON_SAMTEC_TSW-119-09-X-D 65.48,27.9 r270 top locked value="Header 19x2"
CN11 "" CON_SAMTEC_TSW-102-09-X-S 66.75,77.43 r90 top value="Header 2x1 16mm"
CN12 "" CON_SAMTEC_TSW-102-09-X-S 3.25,77.43 r90 top locked value="Header 2x1 16mm"
D1 "" DIO_SOD323 49.8,65.675 r180 top value=BAT60JFILM
D2 "" DIO_SOD323 49.8,63.675 r180 top value=BAT60JFILM
D3 "" DIO_SOD323 49.8,61.675 r180 top value=BAT60JFILM
HW104 "" LOGO_CE 28.225,38.5 r0 top value="LOGO CE"
HW106 "" LOGO_ST 21.725,7.5 r0 top value="LOGO ST"
HW107 "" LOGO_MAIN_1 16.475,55.2 r0 top value="LOGO ESD"
JP1 "" CON_SAMTEC_TSW-102-07-G-S 26,80.04 r180 top value="Shunt not fitted"
JP3 "Shunt Fitted" CON_SAMTEC_TSW-102-07-G-S 10.87,49.49 r270 top locked
JP5 "Shunt Fitted 1-2" CON_SAMTEC_TSW-104-07-X-D 57.86,64.69 r90 top
JP6 "Shunt Fitted" CON_SAMTEC_TSW-102-07-G-S 34.365,41.235 r180 top
JP7 "" CON_SAMTEC_TSW-102-07-G-S 18.22,23.12 r90 top value="Shunt not fitted"
JP8 "Shunt Fitted 1-2" CON_SAMTEC_TSW-103-07-F-S 42.445,41.235 r180 top locked
L1 "" L0603 43.645,28.565 r180 top value=600R@100MHz
L2 "" L0603 43.645,27.065 r180 top value=600R@100MHz
LD1 "" LED_BI-GR_HSMF-A201-A00J1 58.87,78.54 r180 top value=LD_BICOLOR_CMS
LD2 "" LED_0603_GREEN 36.345,52.64 r270 top value=GREEN
LD3 "" LED_0603_GREEN 62.45,70.85 r0 top value=GREEN
LD4 "" LED_0603_RED 47.233,79.63 r270 top value=RED
MP1 "MP1" MIRE_PLACE_SMD_0P8MM 9.025,75.2 r0 top
MP2 "MP2" MIRE_PLACE_SMD_0P8MM 54.075,79.525 r0 top
MP3 "MP3" MIRE_PLACE_SMD_0P8MM 17.12,2.54 r0 top
MP4 "Comment" MIRE_PLACE_SMD_0P8MM 8.95,75.5 r180 bottom
MP5 "Comment" MIRE_PLACE_SMD_0P8MM 19.075,2 r180 bottom
MP6 "Comment" MIRE_PLACE_SMD_0P8MM 61.875,77.875 r180 bottom
Q1 "" NPN_SOT23 47.825,45.275 r90 top value=9013-SOT23
Q2 "" NPN_SOT23 51.37,23.79 r180 top value=9013-SOT23
R1 "" R0603 48.533,79.68 r270 top value=1K
R2 "" R0603 58.12,74.815 r270 top value=330R
R3 "" R0603 59.62,74.815 r270 top value=330R
R4 "" R0402 26.325,74.925 r90 top value=100R
R5 "" R0402 29.875,74.925 r270 top value=3K
R6 "" R0603 45.685,73.27 r270 top value=100K
R7 "" R0603 59.5,70.85 r180 top value=510R
R8 "" R0603 47.585,69.845 r0 top value=10K
R9 "" R0402 15.17,68.515 r180 top value=22R
R10 "" R0402 15.17,67.24 r180 top value=22R
R11 "" R0402 38.35,66.25 r270 top value=4K7
R12 "" R0402 39.4,66.25 r270 top value=2K7
R13 "" R0402 15.17,65.965 r180 top value=22R
R14 "" R0402 23.175,65.9 r0 top value=10K
R15 "" R0402 6.15,64.7 r270 top value=100R
R16 "" R0402 36.225,64.45 r0 top value=4K7
R17 "" R0402 23.175,63.6 r0 top value=10K
R18 "" R0402 16.3,63.425 r180 top value=22R
R19 "" R0402 36.225,63.4 r0 top value=4K7
R20 "" R0402 29.05,61.875 r90 top value=100R
R21 "" R0402 33.2,61.875 r90 top value=10K
R22 "" R0402 5.575,62.15 r0 top value=22R
R23 "" R0402 15.175,61.25 r180 top value=22R
R24 "" R0402 31.55,59 r270 top value=10K
R25 "" R0603 36.345,55.465 r270 top value=510R
R26 "" R0603 34.12,55.54 r180 top value=100K
R27 "" R0603 34.12,53.29 r0 top value=330R
R28 "" R0603 50.625,45.025 r270 top value=100K
R29 "" R0603 50.625,42.55 r90 top value=47K
R30 "" R0603 12.55,43.575 r0 top value=1K
R31 "" R0603 18.22,27.245 r270 top value=10K
R32 "" R0402 23.945,26.84 r0 top value=22R
R33 "​Add 0.5% tolerance resistor" R0603 48.595,24.19 r90 top value="10K - 0.5%"
R34 "​add 0.5% tolerance resistor" R0603 46.62,23.49 r0 top value="33K - 0.5%"
R35 "" R0603 50.87,20.44 r0 top value=820R
SB1 "" SOLDER-BRIDGE_R0603-0R 47.995,53.665 r270 bottom
SB2 "" SOLDER-BRIDGE_R0603-0R 53.575,49.75 r180 bottom
SB3 "" SOLDER-BRIDGE_R0603-0R 52.225,45.225 r270 bottom
SB4 "" SOLDER-BRIDGE_R0603-0R 15.275,43.8 r90 bottom
SB5 "" SOLDER-BRIDGE_R0603-0R 37.97,41.84 r270 bottom
SB6 "" SOLDER-BRIDGE_R0603-0R 53.425,39.575 r180 bottom
SB7 "" SOLDER-BRIDGE_R0603-0R 22.225,27.725 r90 bottom
SB8 "" SOLDER-BRIDGE_R0603-0R 43.645,28.565 r180 bottom
SB9 "" SOLDER-BRIDGE_R0603-0R 23.795,27.715 r270 bottom
SB10 "" SOLDER-BRIDGE_R0603-0R 43.645,27.065 r180 bottom
SB11 "" SOLDER-BRIDGE_R0603-0R 38.36,26.34 r270 bottom
SB12 "" SOLDER-BRIDGE_R0603-0R 35.22,24.29 r90 bottom
SB13 "" SOLDER-BRIDGE_R0603-0R 33.87,24.29 r270 bottom
SB14 "" SOLDER-BRIDGE_R0603-0R 48.595,24.19 r270 bottom
SB15 "" SOLDER-BRIDGE_R0603-0R 26.145,24.34 r180 bottom
SB16 "" SOLDER-BRIDGE_R0603-0R 23.35,21.975 r90 bottom
SB17 "" SOLDER-BRIDGE_R0603-0R 35.22,21.54 r270 bottom
SB18 "" SOLDER-BRIDGE_R0603-0R 33.87,21.54 r90 bottom
SB19 "" SOLDER-BRIDGE_R0603-0R 39.195,20.515 r270 bottom
SB20 "" SOLDER-BRIDGE_R0603-0R 37.845,20.515 r90 bottom
SB21 "" SOLDER-BRIDGE_R0603-0R 20.3,17.75 r270 bottom
SB22 "" SOLDER-BRIDGE_R0603-0R 39.195,17.765 r90 bottom
SB23 "" SOLDER-BRIDGE_R0603-0R 37.845,17.765 r270 bottom
SB24 "" SOLDER-BRIDGE_R0603-0R 36.47,17.765 r90 bottom
SB25 "" SOLDER-BRIDGE_R0603-0R 35.12,17.765 r90 bottom
SB26 "" SOLDER-BRIDGE_R0603-0R 33.77,17.765 r90 bottom
SB27 "" SOLDER-BRIDGE_R0603-0R 32.42,17.765 r90 bottom
SB28 "" SOLDER-BRIDGE_R0603-0R 31.07,17.765 r90 bottom
SB29 "" SOLDER-BRIDGE_R0603-0R 29.72,17.765 r90 bottom
SB30 "" SOLDER-BRIDGE_R0603-0R 28.37,17.765 r90 bottom
SB31 "" SOLDER-BRIDGE_R0603-0R 27.02,17.765 r90 bottom
SB32 "" SOLDER-BRIDGE_R0603-0R 25.67,17.765 r90 bottom
SB33 "" SOLDER-BRIDGE_R0603-0R 53.9,15.125 r90 bottom
SB34 "" SOLDER-BRIDGE_R0603-0R 15.525,5.525 r90 bottom
SB35 "" SOLDER-BRIDGE_R0603-0R 21.25,8.2 r270 bottom
SB36 "" SOLDER-BRIDGE_R0603-0R 15.525,2.575 r90 bottom
SB37 "" SOLDER-BRIDGE_R0603-0R 21.25,4.55 r270 bottom
SB38 "" SOLDER-BRIDGE_R0603-0R 22.575,17.75 r270 bottom
SB39 "" SOLDER-BRIDGE_R0603-0R 15.325,37.8 r90 bottom
SB40 "" SOLDER-BRIDGE_R0603-0R 17.675,36.525 r270 bottom
SB41 "" SOLDER-BRIDGE_R0603-0R 23.175,36.525 r270 bottom
U1 "" ESD_SOT323-5L 16.275,74.65 r270 top value=ESDALC6V1W5
U2 "​" ESD_QFN-6L_1P7X1P5_P050 35.575,75.65 r0 top value=ECMF02-2AMX6
U3 "" ESD_QFN2_1P6X1_P125 37.975,75.35 r0 top value=ESDA7P60-1U1M
U4 "" MOS_SOT23-5L 48.175,72.495 r180 top value=STMPS2151STR
U5 "" ICC_UFBGA201_176+25_10X10_P065 29.7,68.4 r90 top locked value=ST-LINKV3E_SWD
U6 "" ESD_SOT323-5L 18.245,67.89 r270 top value=ESDALC6V1W5
U7 "" REG_SOT23-5L 46.18,62.675 r180 top value=LD3985M33R
U8 "" ESD_ST0201 14.545,63.115 r270 top value=ESDALC6V1-1U2
U9 "" ESD_ST0201 33.72,54.415 r0 top value=ESDALC6V1-1U2
U10 "" ESD_ST0201 49.895,51.365 r90 top value=ESDALC6V1-1U2
U11 "" REG_SOT223-TAB 22.77,43.615 r270 top value=LD1117S50TR
U12 "" ICC_DFN6-EPAD_3X3_P095 32.72,44.99 r270 top value=LD39050PU33R
U13 "STM32G4xx_LQFP64" ICC_LQFP64_10X10_P050_SOCKET_YAMAICHI_IC149-064-069-B5_NM 32.46,24.09 r0 top locked value=STM32G474RET6
U14 "" ICC_SOT23-5L_H1P45 46.37,20.74 r0 top value=TL1431ACL5T
X1 "" OSC_NDK_NZ2520SB_4P 29.675,59.375 r90 top value=25MHz
X2 "" CRY_NX3215SA_2P 28.045,13.515 r0 top value=NX3215SA-32.768K
X3 "" CRY_NX2016SA_4P 34.495,13.59 r270 top value=24MHz

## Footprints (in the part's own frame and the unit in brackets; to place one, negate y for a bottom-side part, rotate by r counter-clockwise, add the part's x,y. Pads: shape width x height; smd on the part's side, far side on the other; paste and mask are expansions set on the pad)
C0402 [mm]
  rect 0.51x0.56 smd mask+0.05: 1(-0.45,0) 2(0.45,0)
  silkscreen extent -0.72,-0.35 0.72,0.35, body extent -0.5,-0.3 0.5,0.3, height 0.4
C0603 [mm]
  rect 0.64x0.89 smd mask+0.05: 1(-0.7,0) 2(0.7,0)
  silkscreen extent -1.05,-0.55 1.02,0.55, body extent -0.9,-0.5 0.9,0.5, height 1.4
C0805 [mm]
  rect 0.9x1.4 smd mask+0.05: 1(-0.85,0) 2(0.85,0)
  silkscreen extent -1.3,-0.77 1.3,0.77, body extent -1.1,-0.7 1.1,0.7, height 1.35
C1206_H1P15 [mm]
  rect 1.4x1.78 smd mask+0.05: 1(-1.4,0) 2(1.4,0)
  silkscreen extent -2.12,-0.97 2.15,0.97, body extent -1.7,-0.9 1.7,0.9, height 1.35
CON_SAMTEC_SSW-106-03-X-S [mm]
  rect 1.85x1.85 / inner round 1.85 / far side rect 1.85x1.85 hole 1.1 mask+0.05: 1(-6.35,0)
  round 1.85 hole 1.1 mask+0.05: 2(-3.81,0) 3(-1.27,0) 4(1.27,0) 5(3.81,0) 6(6.35,0)
  silkscreen extent -7.88,-1.2 7.88,1.2, body extent -7.88,-1.21 7.88,1.21, height 8.51
CON_SAMTEC_SSW-108-03-X-S [mm]
  rect 1.85x1.85 / inner round 1.85 / far side rect 1.85x1.85 hole 1.1 mask+0.05: 1(-8.89,0)
  round 1.85 hole 1.1 mask+0.05: 2(-6.35,0) 3(-3.81,0) 4(-1.27,0) 5(1.27,0) 6(3.81,0) 7(6.35,0) 8(8.89,0)
  silkscreen extent -10.42,-1.2 10.42,1.2, body extent -10.42,-1.21 10.42,1.21, height 8.51
CON_SAMTEC_SSW-110-03-X-S [mm]
  rect 1.85x1.85 / inner round 1.85 / far side rect 1.85x1.85 hole 1.1 mask+0.05: 1(-11.43,0)
  round 1.85 hole 1.1 mask+0.05: 2(-8.89,0) 3(-6.35,0) 4(-3.81,0) 5(-1.27,0) 6(1.27,0) 7(3.81,0) 8(6.35,0) 9(8.89,0) 10(11.43,0)
  silkscreen extent -12.96,-1.2 12.96,1.2, body extent -12.96,-1.21 12.96,1.21, height 8.51
CON_SAMTEC_TSW-102-07-G-S [mm]
  rect 1.85x1.85 / inner round 1.85 / far side rect 1.85x1.85 hole 1 mask+0.05: 1(-1.27,0)
  round 1.85 hole 1 mask+0.05: 2(1.27,0)
  silkscreen extent -2.58,-1.3 2.58,1.3, body extent -2.67,-1.3 2.58,1.3, height 8.38
CON_SAMTEC_TSW-102-09-X-S [mm]
  rect 1.85x1.85 / inner round 1.85 / far side rect 1.85x1.85 hole 1 mask+0.05: 1(-1.27,0)
  round 1.85 hole 1 mask+0.05: 2(1.27,0)
  silkscreen extent -2.64,-1.37 2.64,1.37, body extent -2.67,-1.3 2.58,1.3, height 8.38
CON_SAMTEC_TSW-103-07-F-S [mm]
  rect 1.85x1.85 / inner round 1.85 / far side rect 1.85x1.85 hole 1 mask+0.05: 1(-2.54,0)
  round 1.85 hole 1 mask+0.05: 2(0,0) 3(2.54,0)
  silkscreen extent -3.85,-1.3 3.85,1.3, body extent -3.91,-1.37 3.91,1.37, height 8.38
CON_SAMTEC_TSW-104-07-G-S [mm]
  rect 1.85x1.85 / inner round 1.85 / far side rect 1.85x1.85 hole 1 mask+0.05: 1(-3.81,0)
  round 1.85 hole 1 mask+0.05: 2(-1.27,0) 3(1.27,0) 4(3.81,0)
  silkscreen extent -5.12,-1.3 5.12,1.3, body extent -5.21,-1.37 5.18,1.37, height 8.38
CON_SAMTEC_TSW-104-07-X-D [mm]
  rect 1.85x1.85 / inner round 1.85 / far side rect 1.85x1.85 hole 1 mask+0.05: 1(-3.81,-1.27)
  round 1.85 hole 1 mask+0.05: 2(-3.81,1.27) 3(-1.27,-1.27) 4(-1.27,1.27) 5(1.27,-1.27) 6(1.27,1.27) 7(3.81,-1.27) 8(3.81,1.27)
  silkscreen extent -5.08,-2.54 5.08,2.54, body extent -5.08,-2.54 5.08,2.54, height 8.38
CON_SAMTEC_TSW-119-09-X-D [mm]
  rect 1.85x1.85 / inner round 1.85 / far side rect 1.85x1.85 hole 1 mask+0.05: 1(-22.86,-1.27)
  round 1.85 hole 1 mask+0.05: 2(-22.86,1.27) 3(-20.32,-1.27) 4(-20.32,1.27) 5(-17.78,-1.27) 6(-17.78,1.27) 7(-15.24,-1.27) 8(-15.24,1.27) 9(-12.7,-1.27) 10(-12.7,1.27) 11(-10.16,-1.27) 12(-10.16,1.27) 13(-7.62,-1.27) 14(-7.62,1.27) 15(-5.08,-1.27) 16(-5.08,1.27) 17(-2.54,-1.27) 18(-2.54,1.27) 19(0,-1.27) 20(0,1.27) 21(2.54,-1.27) 22(2.54,1.27) 23(5.08,-1.27) 24(5.08,1.27) 25(7.62,-1.27) 26(7.62,1.27) 27(10.16,-1.27) 28(10.16,1.27) 29(12.7,-1.27) 30(12.7,1.27) 31(15.24,-1.27) 32(15.24,1.27) 33(17.78,-1.27) 34(17.78,1.27) 35(20.32,-1.27) 36(20.32,1.27) 37(22.86,-1.27) 38(22.86,1.27)
  silkscreen extent -24.13,-2.54 24.13,2.54, body extent -24.13,-2.55 24.13,2.54, height 8.38
CON_STDC14_Receiver_MEDIUM [mm] "compatible with FTSH-107-01-L-DV,-K,-A,-P,-ES"
  round 0 hole 1.19 unplated mask+0.05: 0(-5.445,0) 0(5.445,0)
  round 0 hole 0.97 unplated mask+0.05: 0(-3.175,0) 0(3.175,0)
  rect 0.74x2.79 smd mask+0.05: 1(-3.81,-2.032) 2(-3.81,2.032) 3(-2.54,-2.032) 4(-2.54,2.032) 5(-1.27,-2.032) 6(-1.27,2.032) 7(0,-2.032) 8(0,2.032) 9(1.27,-2.032) 10(1.27,2.032) 11(2.54,-2.032) 12(2.54,2.032) 13(3.81,-2.032) 14(3.81,2.032)
  silkscreen extent -6.3,-2.39 6.3,2.39, body extent -6.3,-2.92 6.3,2.92, height 6.6
CON_USBMICROB_MOLEX_105017-0001_H2P90 [mm]
  rect 0.4x1.35 smd mask+0.05: 1(-1.3,4.15) 2(-0.65,4.15) 3(0,4.15) 4(0.65,4.15) 5(1.3,4.15)
  round 1.5 hole 0.9 mask+0.05: 6(-2.5,4.15) 7(2.5,4.15)
  oval 1.2x1.9 hole 0.6 slot 1.3 at 90 deg mask+0.05: 8(3.5,1.45) 9(-3.5,1.45)
  rect 1.5x1.9 smd mask+0.05: 10(-1,1.45) 11(1,1.45)
  Top Layer region: -3.5,2.4 -2.3,2.4 -2.3,0.5 -3.5,0.5 -3.5,2.4
  Top Layer region: 2.3,2.4 3.5,2.4 3.5,0.5 2.3,0.5 2.3,2.4
  silkscreen extent -4,-0.7 4,4.6, body extent -4.1,-1.15 4.1,4.66, height 2.9
CRY_NX2016SA_4P [mm]
  rect 0.85x0.75 smd mask+0.05: 1(-0.675,-0.525) 2(0.675,-0.525) 3(0.675,0.525) 4(-0.675,0.525)
  silkscreen extent -1.22,-1.02 1.05,0.85, body extent -1.05,-0.85 1.05,0.85, height 0.7
CRY_NX3215SA_2P [mm]
  rect 1x1.8 smd mask+0.05: 1(-1.25,0) 2(1.25,0)
  silkscreen extent -0.63,-0.8 0.63,0.8, body extent -1.65,-0.8 1.65,0.8, height 0.9
DIO_SOD323 [mm]
  rect 1.06x0.54 smd mask+0.05: 1(-1.07,0) 2(1.07,0)
  silkscreen extent -0.9,-0.72 0.9,0.72, body extent -1.3,-0.78 1.3,0.78, height 1.17
ESD_QFN2_1P6X1_P125 [mm]
  rect 0.55x0.8 smd mask+0.05: 1(-0.625,0) 2(0.625,0)
  silkscreen extent -1,-0.55 0.85,0.55, body extent -0.85,-0.55 0.85,0.55, height 0.61
ESD_QFN-6L_1P7X1P5_P050 [mm]
  rect 0.25x0.6 smd mask+0.05: 1(-0.5,-0.65) 2(0,-0.65) 3(0.5,-0.65) 4(0.5,0.65) 5(0,0.65) 6(-0.5,0.65)
  silkscreen extent -0.9,-0.8 0.9,0.8, body extent -0.9,-0.8 0.9,0.8, height 0.56
ESD_SOT323-5L [mm]
  rect 0.4x1.2 smd mask+0.05: 1(-0.65,-0.85) 2(0,-0.85) 3(0.65,-0.85) 4(0.65,0.85) 5(-0.65,0.85)
  silkscreen extent -1.22,-1.21 1.22,0.77, body extent -1.15,-1.05 1.15,1.05, height 1.1
ESD_ST0201 [mm]
  rect 0.425x0.33 smd mask+0.05: 1(-0.312,0) 2(0.312,0)
  silkscreen extent -0.55,-0.3 0.33,0.3, body extent -0.34,-0.18 0.34,0.18, height 0.34
ICC_DFN6-EPAD_3X3_P095 [mm]
  rect 0.45x0.5 smd mask+0.05: 1(-0.95,-1.3) 2(0,-1.3) 3(0.95,-1.3) 4(0.95,1.3) 5(0,1.3) 6(-0.95,1.3)
  rect 2.5x1.7 smd mask+0.05: EP(0,0)
  silkscreen extent -1.55,-1.55 1.55,1.55, body extent -1.55,-1.55 1.55,1.55, height 1
ICC_LQFP64_10X10_P050_SOCKET_YAMAICHI_IC149-064-069-B5_NM [mm]
  rect 1x2.5 smd rot 45 mask+0.05: 0(-6,-6) 0(6,6)
  rect 1x2.5 smd rot 135 mask+0.05: 0(-6,6) 0(6,-6)
  round 0.5 hole 1 unplated mask+0.05: 0(0,-3.1) 0(0,3.1)
  rect 0.3x1.7 smd mask+0.05: 1(-3.75,-5.9) 2(-3.25,-5.9) 3(-2.75,-5.9) 4(-2.25,-5.9) 5(-1.75,-5.9) 6(-1.25,-5.9) 7(-0.75,-5.9) 8(-0.25,-5.9) 9(0.25,-5.9) 10(0.75,-5.9) 11(1.25,-5.9) 12(1.75,-5.9) 13(2.25,-5.9) 14(2.75,-5.9) 15(3.25,-5.9) 16(3.75,-5.9) 33(3.75,5.9) 34(3.25,5.9) 35(2.75,5.9) 36(2.25,5.9) 37(1.75,5.9) 38(1.25,5.9) 39(0.75,5.9) 40(0.25,5.9) 41(-0.25,5.9) 42(-0.75,5.9) 43(-1.25,5.9) 44(-1.75,5.9) 45(-2.25,5.9) 46(-2.75,5.9) 47(-3.25,5.9) 48(-3.75,5.9)
  rect 1.7x0.3 smd mask+0.05: 17(5.9,-3.75) 18(5.9,-3.25) 19(5.9,-2.75) 20(5.9,-2.25) 21(5.9,-1.75) 22(5.9,-1.25) 23(5.9,-0.75) 24(5.9,-0.25) 25(5.9,0.25) 26(5.9,0.75) 27(5.9,1.25) 28(5.9,1.75) 29(5.9,2.25) 30(5.9,2.75) 31(5.9,3.25) 32(5.9,3.75) 49(-5.9,3.75) 50(-5.9,3.25) 51(-5.9,2.75) 52(-5.9,2.25) 53(-5.9,1.75) 54(-5.9,1.25) 55(-5.9,0.75) 56(-5.9,0.25) 57(-5.9,-0.25) 58(-5.9,-0.75) 59(-5.9,-1.25) 60(-5.9,-1.75) 61(-5.9,-2.25) 62(-5.9,-2.75) 63(-5.9,-3.25) 64(-5.9,-3.75)
  silkscreen extent -5.05,-5.05 5.05,5.05, body extent -6,-6 6,6, height 1.6
ICC_SOT23-5L_H1P45 [mm]
  rect 0.6x1.3 smd mask+0.05: 1(-0.95,-1.1) 2(0,-1.1) 3(0.95,-1.1) 4(0.95,1.1) 5(-0.95,1.1)
  silkscreen extent -1.75,-1.68 1.6,0.97, body extent -1.52,-1.25 1.52,1.25, height 1.45
ICC_UFBGA201_176+25_10X10_P065 [mm] "IPC"
  round 0.25 smd mask+0.05: A1(-4.55,4.55) A2(-3.9,4.55) A3(-3.25,4.55) A4(-2.6,4.55) A5(-1.95,4.55) A6(-1.3,4.55) A7(-0.65,4.55) A8(0,4.55) A9(0.65,4.55) A10(1.3,4.55) A11(1.95,4.55) A12(2.6,4.55) A13(3.25,4.55) A14(3.9,4.55) A15(4.55,4.55) B1(-4.55,3.9) B2(-3.9,3.9) B3(-3.25,3.9) B4(-2.6,3.9) B5(-1.95,3.9) B6(-1.3,3.9) B7(-0.65,3.9) B8(0,3.9) B9(0.65,3.9) B10(1.3,3.9) B11(1.95,3.9) B12(2.6,3.9) B13(3.25,3.9) B14(3.9,3.9) B15(4.55,3.9) C1(-4.55,3.25) C2(-3.9,3.25) C3(-3.25,3.25) C4(-2.6,3.25) C5(-1.95,3.25) C6(-1.3,3.25) C7(-0.65,3.25) C8(0,3.25) C9(0.65,3.25) C10(1.3,3.25) C11(1.95,3.25) C12(2.6,3.25) C13(3.25,3.25) C14(3.9,3.25) C15(4.55,3.25) D1(-4.55,2.6) D2(-3.9,2.6) D3(-3.25,2.6) D4(-2.6,2.6) D5(-1.95,2.6) D6(-1.3,2.6) D7(-0.65,2.6) D8(0,2.6) D9(0.65,2.6) D10(1.3,2.6) D11(1.95,2.6) D12(2.6,2.6) D13(3.25,2.6) D14(3.9,2.6) D15(4.55,2.6) E1(-4.55,1.95) E2(-3.9,1.95) E3(-3.25,1.95) E4(-2.6,1.95) E12(2.6,1.95) E13(3.25,1.95) E14(3.9,1.95) E15(4.55,1.95) F1(-4.55,1.3) F2(-3.9,1.3) F3(-3.25,1.3) F4(-2.6,1.3) F6(-1.3,1.3) F7(-0.65,1.3) F8(0,1.3) F9(0.65,1.3) F10(1.3,1.3) F12(2.6,1.3) F13(3.25,1.3) F14(3.9,1.3) F15(4.55,1.3) G1(-4.55,0.65) G2(-3.9,0.65) G3(-3.25,0.65) G4(-2.6,0.65) G6(-1.3,0.65) G7(-0.65,0.65) G8(0,0.65) G9(0.65,0.65) G10(1.3,0.65) G12(2.6,0.65) G13(3.25,0.65) G14(3.9,0.65) G15(4.55,0.65) H1(-4.55,0) H2(-3.9,0) H3(-3.25,0) H4(-2.6,0) H6(-1.3,0) H7(-0.65,0) H8(0,0) H9(0.65,0) H10(1.3,0) H12(2.6,0) H13(3.25,0) H14(3.9,0) H15(4.55,0) J1(-4.55,-0.65) J2(-3.9,-0.65) J3(-3.25,-0.65) J4(-2.6,-0.65) J6(-1.3,-0.65) J7(-0.65,-0.65) J8(0,-0.65) J9(0.65,-0.65) J10(1.3,-0.65) J12(2.6,-0.65) J13(3.25,-0.65) J14(3.9,-0.65) J15(4.55,-0.65) K1(-4.55,-1.3) K2(-3.9,-1.3) K3(-3.25,-1.3) K4(-2.6,-1.3) K6(-1.3,-1.3) K7(-0.65,-1.3) K8(0,-1.3) K9(0.65,-1.3) K10(1.3,-1.3) K12(2.6,-1.3) K13(3.25,-1.3) K14(3.9,-1.3) K15(4.55,-1.3) L1(-4.55,-1.95) L2(-3.9,-1.95) L3(-3.25,-1.95) L4(-2.6,-1.95) L12(2.6,-1.95) L13(3.25,-1.95) L14(3.9,-1.95) L15(4.55,-1.95) M1(-4.55,-2.6) M2(-3.9,-2.6) M3(-3.25,-2.6) M4(-2.6,-2.6) M5(-1.95,-2.6) M6(-1.3,-2.6) M7(-0.65,-2.6) M8(0,-2.6) M9(0.65,-2.6) M10(1.3,-2.6) M11(1.95,-2.6) M12(2.6,-2.6) M13(3.25,-2.6) M14(3.9,-2.6) M15(4.55,-2.6) N1(-4.55,-3.25) N2(-3.9,-3.25) N3(-3.25,-3.25) N4(-2.6,-3.25) N5(-1.95,-3.25) N6(-1.3,-3.25) N7(-0.65,-3.25) N8(0,-3.25) N9(0.65,-3.25) N10(1.3,-3.25) N11(1.95,-3.25) N12(2.6,-3.25) N13(3.25,-3.25) N14(3.9,-3.25) N15(4.55,-3.25) P1(-4.55,-3.9) P2(-3.9,-3.9) P3(-3.25,-3.9) P4(-2.6,-3.9) P5(-1.95,-3.9) P6(-1.3,-3.9) P7(-0.65,-3.9) P8(0,-3.9) P9(0.65,-3.9) P10(1.3,-3.9) P11(1.95,-3.9) P12(2.6,-3.9) P13(3.25,-3.9) P14(3.9,-3.9) P15(4.55,-3.9) R1(-4.55,-4.55) R2(-3.9,-4.55) R3(-3.25,-4.55) R4(-2.6,-4.55) R5(-1.95,-4.55) R6(-1.3,-4.55) R7(-0.65,-4.55) R8(0,-4.55) R9(0.65,-4.55) R10(1.3,-4.55) R11(1.95,-4.55) R12(2.6,-4.55) R13(3.25,-4.55) R14(3.9,-4.55) R15(4.55,-4.55)
  silkscreen extent -5.22,-5.07 5.07,5.23, body extent -5.07,-5.07 5.07,5.07, height 0.61
L0603 [mm]
  rect 0.8x0.95 smd mask+0.05: 1(-0.8,0) 2(0.8,0)
  silkscreen extent -1.33,-0.6 1.33,0.6, body extent -0.87,-0.47 0.87,0.47, height 0.95
LED_0603_GREEN [mm]
  rect 0.8x0.8 smd mask+0.05: 1(-0.75,0) 2(0.75,0)
  silkscreen extent -0.25,-0.4 1.25,0.4, body extent -0.8,-0.4 0.8,0.4, height 0.6
LED_0603_RED [mm]
  rect 0.8x0.8 smd mask+0.05: 1(-0.75,0) 2(0.75,0)
  silkscreen extent -0.25,-0.4 1.25,0.4, body extent -0.8,-0.4 0.8,0.4, height 0.6
LED_BI-GR_HSMF-A201-A00J1 [mm]
  rect 1.1x1.5 smd mask+0.05: 1(-0.75,-1.5) 2(-0.75,1.5) 3(0.75,1.5) 4(0.75,-1.5)
  silkscreen extent -1.65,-1.85 1.65,1.85, body extent -1.5,-1.85 1.5,1.85, height 2.1
LOGO_CE [mm]
  silkscreen extent -1.61,-1.37 1.85,1.07
LOGO_MAIN_1 [mm]
  silkscreen extent -3.36,-2.51 3.52,3.76
LOGO_ST [mm]
  silkscreen extent -6.18,-2.95 5.25,3.14
MIRE_PLACE_SMD_0P8MM [mm]
  round 0.8 smd paste-10 mask+0.2: 1(0,0)
  Top Layer keep-out circle w0.01: c0,0 r0.804
MOS_SOT23-5L [mm]
  rect 0.6x1.3 smd mask+0.05: 1(-0.95,-1.1) 2(0,-1.1) 3(0.95,-1.1) 4(0.95,1.1) 5(-0.95,1.1)
  silkscreen extent -1.6,-0.95 1.6,0.97, body extent -1.52,-1.25 1.52,1.25, height 1.45
NPN_SOT23 [mm]
  rect 1x1.4 smd mask+0.05: 1(-0.95,-1.1) 2(0.95,-1.1) 3(0,1.1)
  silkscreen extent -1.63,-0.82 1.63,0.82, body extent -1.56,-1.25 1.56,1.25, height 1.1
OSC_NDK_NZ2520SB_4P [mm]
  rect 1x1 smd mask+0.05: 1(-0.825,-0.625) 2(0.825,-0.625) 3(0.825,0.625) 4(-0.825,0.625)
  silkscreen extent -1.43,-1.22 1.2,1.05, body extent -1.3,-1.05 1.3,1.05, height 0.91
R0402 [mm]
  rect 0.51x0.7 smd mask+0.05: 1(-0.45,0) 2(0.45,0)
  silkscreen extent -0.72,-0.43 0.72,0.43, body extent -0.52,-0.3 0.52,0.3, height 0.4
R0603 [mm]
  rect 0.64x1 smd mask+0.05: 1(-0.7,0) 2(0.7,0)
  silkscreen extent -1.05,-0.58 1.05,0.58, body extent -0.9,-0.5 0.9,0.5, height 0.56
REG_SOT23-5L [mm]
  rect 0.6x1.3 smd mask+0.05: 1(-0.95,-1.1) 2(0,-1.1) 3(0.95,-1.1) 4(0.95,1.1) 5(-0.95,1.1)
  silkscreen extent -1.6,-0.95 1.6,0.97, body extent -1.52,-1.25 1.52,1.25, height 1.1
REG_SOT223-TAB [mm]
  rect 1.5x1.65 smd mask+0.05: 1(-2.3,-3.175) 2(0,-3.175) 3(2.3,-3.175)
  rect 3.5x1.65 smd mask+0.05: 4(0,3.175)
  silkscreen extent -3.35,-2.15 3.35,2.12, body extent -3.35,-3.48 3.35,3.48, height 1.8
SOLDER-BRIDGE_R0603-0R [mil]
  round 10 smd paste-393.7: 1(-19.68,0) 2(23.62,0)
  Top Layer region: -5.91,19.68 13.78,0 -5.91,-19.68 47.24,-19.68 47.24,19.68 -5.91,19.68
  Top Layer region: -47.24,-19.68 -47.24,19.68 -15.75,19.68 3.94,0 -15.75,-19.68 -47.24,-19.68
  silkscreen extent -50,-23 50,23, body extent -36,-20 36,20, height 22
SWI_WEALTHMETAL_TD-0341_4P_BLACK [mm]
  rect 1.52x2.16 smd mask+0.05: 1(-2.25,-4.75) 2(-2.25,4.75) 3(2.25,-4.75) 4(2.25,4.75)
  silkscreen extent -3,-3.5 3,3.5, body extent -3,-5.15 3,5.15, height 7.55
SWI_WEALTHMETAL_TD-0341_4P_BLUE [mm]
  rect 1.52x2.16 smd mask+0.05: 1(-2.25,-4.75) 2(-2.25,4.75) 3(2.25,-4.75) 4(2.25,4.75)
  silkscreen extent -3,-3.5 3,3.5, body extent -3,-5.15 3,5.15, height 7.55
